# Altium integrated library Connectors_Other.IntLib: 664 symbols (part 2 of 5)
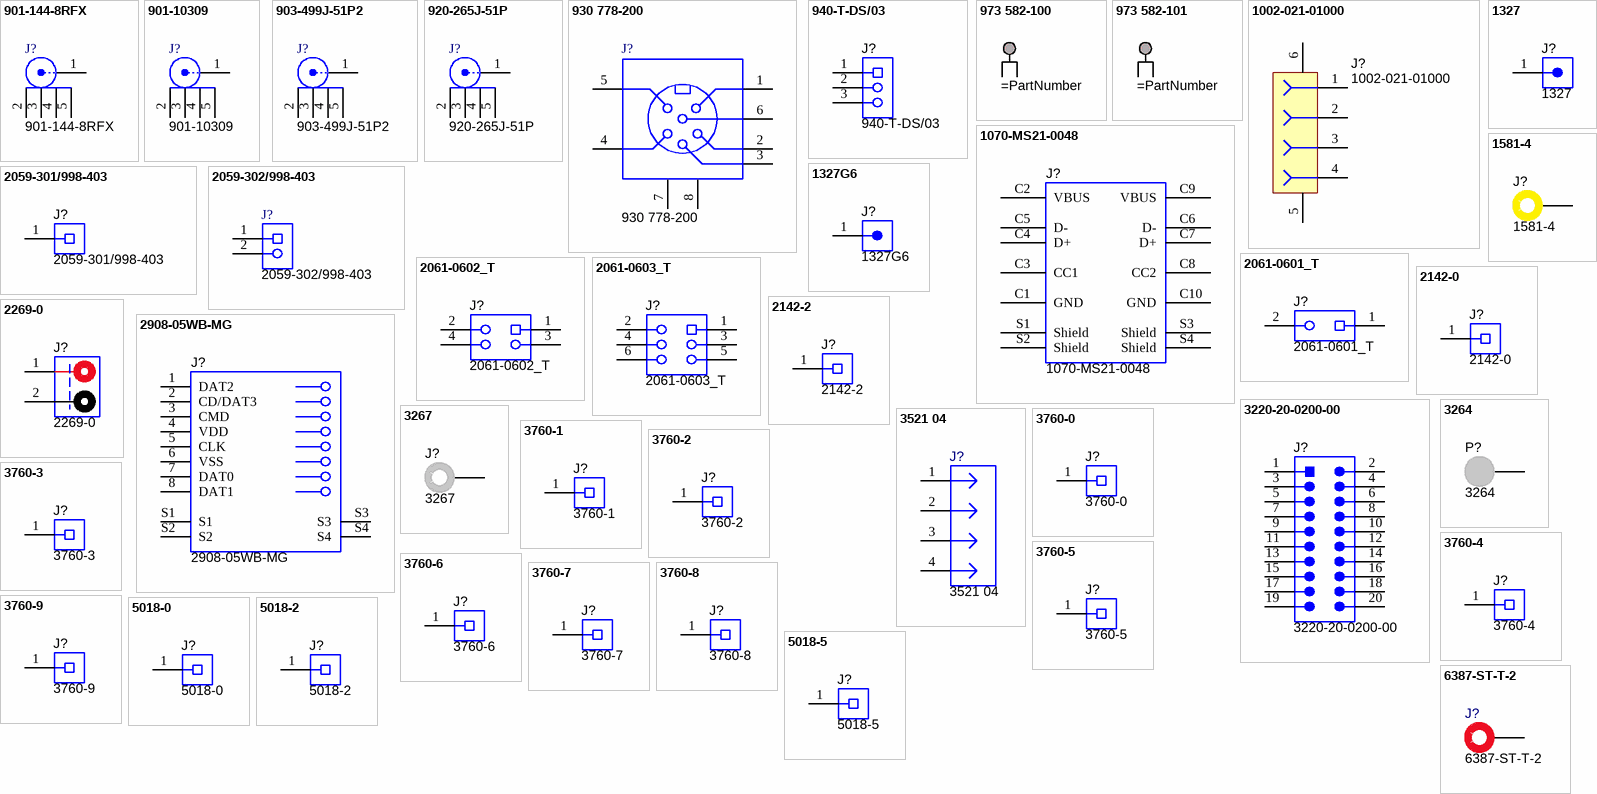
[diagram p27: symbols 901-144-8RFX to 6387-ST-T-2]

## 5018-0
designator J?
Hex Head Binding Post, 1x1, Black, TH; Manufacturer: Pomona Electronics; SymbolCreator: a0799628; CompType: Connector; Current_A: 30; Green_Lifecycle: Not Set; Green_REACh: Incomplete
footprint Pomona_5018-0
pins: 1

## 5018-2
designator J?
Hex Head Binding Post, 1x1, Red, TH; Manufacturer: Pomona Electronics; SymbolCreator: a0799628; CompType: Connector; Current_A: 30; Green_Lifecycle: Not Set; Green_REACh: Incomplete
footprint Pomona_5018-2
pins: 1

## 5018-5
designator J?
Hex Head Binding Post, 1x1, Green, TH; Manufacturer: Pomona Electronics; SymbolCreator: a0799628; CompType: Connector; Current_A: 30
footprint Pomona_5018-5
pins: 1

## 6387-ST-T-2
designator J?
Banana Jack For Sheathed Banana Plugs, 4mm, TH; Manufacturer: Pomona Electronics; SymbolCreator: a0412235; ContactFinish: Tin
footprint Pomona_6387-ST-T-2
pins: 1

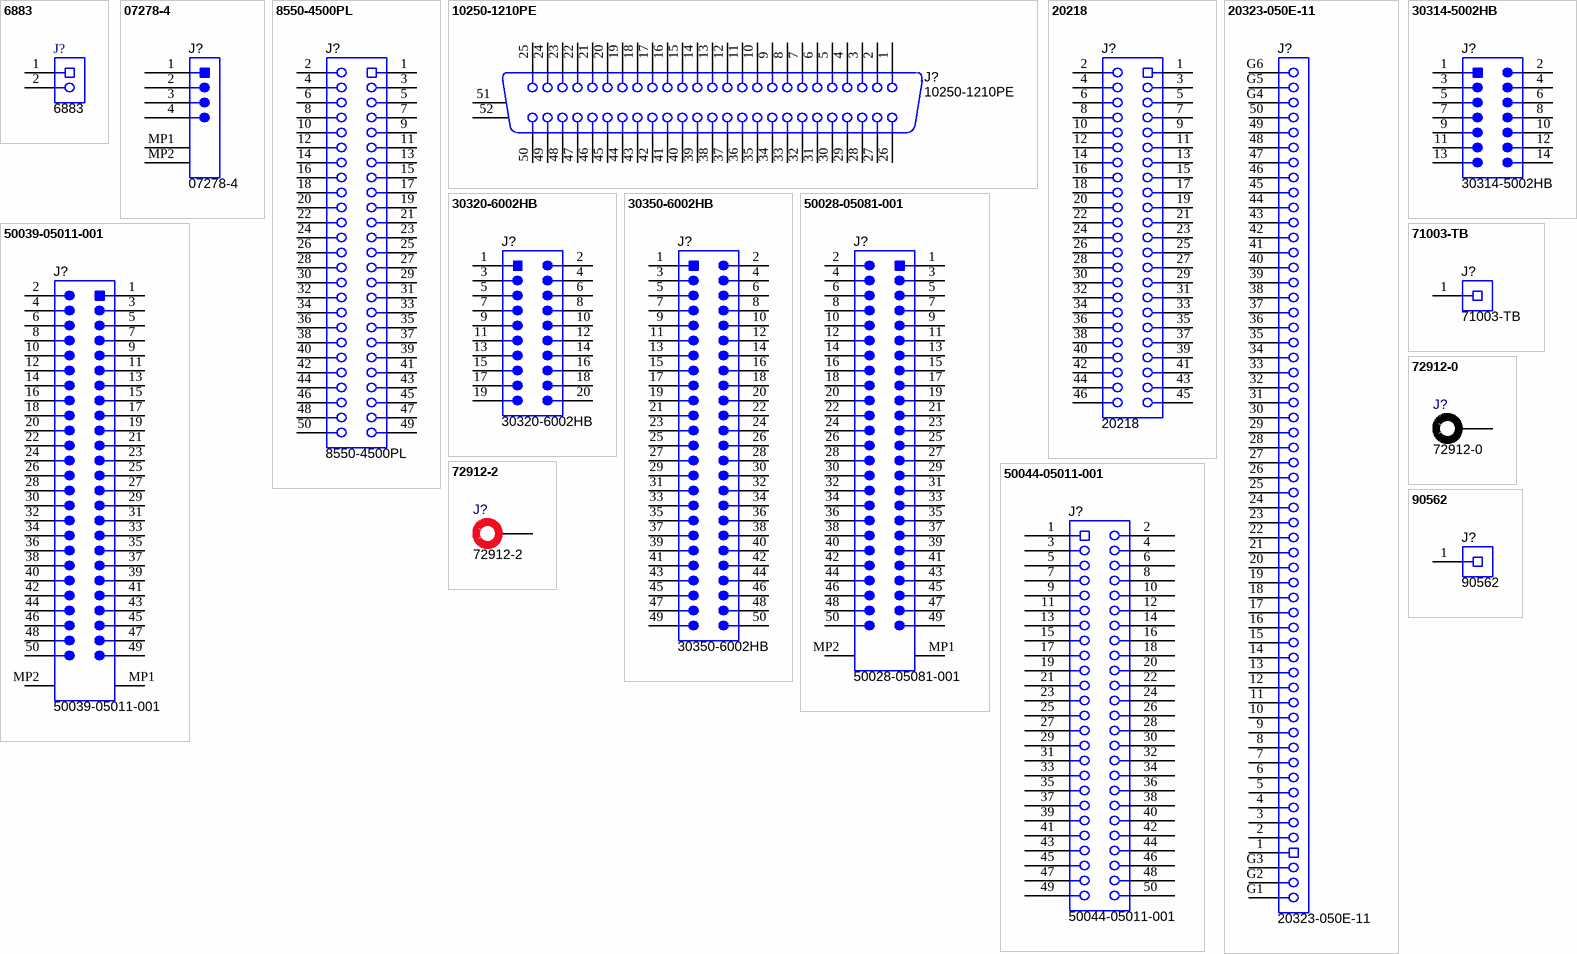
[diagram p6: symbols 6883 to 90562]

## 6883
designator J?
Dual Binding Posts with Base, 2x1, TH; Manufacturer: Pomona Electronics; SymbolCreator: a0412235; CompType: Connector; Green_Lifecycle: Not Set; Green_REACh: Incomplete
footprint Pomona_6883
pins: 1, 2

## 07278-4
designator J?
Header, 1mm, 4x1, R/A, SMT; Manufacturer: 4UCON Technology; SymbolCreator: Altium; Pitch_mm: 1; Gender: Male; ContactFinish: Tin; Voltage_V: 50; Cert_UL: Y
footprint 4UCON_07278-4
pins: 1, 2, 3, 4, MP1, MP2

## 8550-4500PL
designator J?
Receptacle, 2.54mm, 25x2, Gold, TH; Manufacturer: 3M; SymbolCreator: a0412235; Pitch_mm: 2.54; Gender: Female; Row_Count: 2
footprint 3M_8550-4500PL
pins: 1, 2, 3, 4, 5, 6, 7, 8, 9, 10, 11, 12, 13, 14, 15, 16, 17, 18, 19, 20, 21, 22, 23, 24, 25, 26, 27, 28, 29, 30, 31, 32, 33, 34, 35, 36, 37, 38, 39, 40, 41, 42, 43, 44, 45, 46, 47, 48, 49, 50

## 10250-1210PE
designator J?
Connector, Receptacle, D-Sub, 50POS, R/A, SMT; Manufacturer: 3M; SymbolCreator: a0412235
footprint CONN_3M_10250-1210PE
pins: 1, 2, 3, 4, 5, 6, 7, 8, 9, 10, 11, 12, 13, 14, 15, 16, 17, 18, 19, 20, 21, 22, 23, 24, 25, 26, 27, 28, 29, 30, 31, 32, 33, 34, 35, 36, 37, 38, 39, 40, 41, 42, 43, 44, 45, 46, 47, 48, 49, 50, 51, 52

## 20218
designator J?
Receptacle, 2.54 mm, 23x2, Gold, TH; Manufacturer: 4UCON Technology; SymbolCreator: Altium
footprint 4UCON_20218
pins: 1, 2, 3, 4, 5, 6, 7, 8, 9, 10, 11, 12, 13, 14, 15, 16, 17, 18, 19, 20, 21, 22, 23, 24, 25, 26, 27, 28, 29, 30, 31, 32, 33, 34, 35, 36, 37, 38, 39, 40, 41, 42, 43, 44, 45, 46

## 20323-050E-11
designator J?
FPL, Receptacle SMT 0.5 mm pitch, 50 pos; Manufacturer: I-PEX; SymbolCreator: a0799628
footprint I-PEX_20323-050E-11
pins: 1, 2, 3, 4, 5, 6, 7, 8, 9, 10, 11, 12, 13, 14, 15, 16, 17, 18, 19, 20, 21, 22, 23, 24, 25, 26, 27, 28, 29, 30, 31, 32, 33, 34, 35, 36, 37, 38, 39, 40, 41, 42, 43, 44, 45, 46, 47, 48, 49, 50, G1, G2, G3, G4, G5, G6

## 30314-5002HB
designator J?
Header(shrouded), 2.54mm, 7x2, Gold, R/A,  TH; Manufacturer: 3M; SymbolCreator: a0412235; Pitch_mm: 2.54; Gender: Male; Shrouded: Y; Row_Count: 2; Current_A: 1
footprint 3M_30314-5002
pins: 1, 2, 3, 4, 5, 6, 7, 8, 9, 10, 11, 12, 13, 14

## 30320-6002HB
designator J?
Straight Low Profile Header, 10x2 Position, 2.54 mm Pitch, TH; Manufacturer: 3M; SymbolCreator: a0412235
footprint 3M_30320-6002HB
pins: 1, 2, 3, 4, 5, 6, 7, 8, 9, 10, 11, 12, 13, 14, 15, 16, 17, 18, 19, 20

## 30350-6002HB
designator J?
Header (Shrouded), 2.54 mm, 25x2, Gold, TH; Manufacturer: 3M; SymbolCreator: a0799628
footprint 3M_30350-6002HB
pins: 1, 2, 3, 4, 5, 6, 7, 8, 9, 10, 11, 12, 13, 14, 15, 16, 17, 18, 19, 20, 21, 22, 23, 24, 25, 26, 27, 28, 29, 30, 31, 32, 33, 34, 35, 36, 37, 38, 39, 40, 41, 42, 43, 44, 45, 46, 47, 48, 49, 50

## 50028-05081-001
designator J?
Plug, 0.5mm, 25x2, Gold, SMT; Manufacturer: ACES Electronics; SymbolCreator: Altium; Pitch_mm: 0.5; Gender: Male; Row_Count: 2; Cert_UL: Y
footprint Aces_50028-050
pins: 1, 2, 3, 4, 5, 6, 7, 8, 9, 10, 11, 12, 13, 14, 15, 16, 17, 18, 19, 20, 21, 22, 23, 24, 25, 26, 27, 28, 29, 30, 31, 32, 33, 34, 35, 36, 37, 38, 39, 40, 41, 42, 43, 44, 45, 46, 47, 48, 49, 50, MP1, MP2

## 50039-05011-001
designator J?
Plug, 0.5mm, 25x2, Gold, SMD; Manufacturer: ACES Electronics; SymbolCreator: Altium; Pitch_mm: 0.5; Gender: Male; Shrouded: Y; Row_Count: 2; RowSpacing_mm: 3.675; Voltage_V: 50
footprint Aces_50039-05011-001
pins: 1, 2, 3, 4, 5, 6, 7, 8, 9, 10, 11, 12, 13, 14, 15, 16, 17, 18, 19, 20, 21, 22, 23, 24, 25, 26, 27, 28, 29, 30, 31, 32, 33, 34, 35, 36, 37, 38, 39, 40, 41, 42, 43, 44, 45, 46, 47, 48, 49, 50, MP1, MP2

## 50044-05011-001
designator J?
Receptacle, 0.5mm, 25x2, Gold, SMD; Manufacturer: ACES Electronics; SymbolCreator: Altium; Pitch_mm: 0.5; Gender: Female; Row_Count: 2; RowSpacing_mm: 4.2; Voltage_V: 50; Cert_UL: Y
footprint Aces_50044-05011-001
pins: 1, 2, 3, 4, 5, 6, 7, 8, 9, 10, 11, 12, 13, 14, 15, 16, 17, 18, 19, 20, 21, 22, 23, 24, 25, 26, 27, 28, 29, 30, 31, 32, 33, 34, 35, 36, 37, 38, 39, 40, 41, 42, 43, 44, 45, 46, 47, 48, 49, 50

## 71003-TB
designator J?
Locktite Copper Cone Screw Lug for Conductor Range 14-8, TH; Manufacturer: Thomas & Betts; SymbolCreator: a0799628; CompType: Connector; Gender: Female; Row_Count: 1; Cert_CSA: Y
footprint TB_71003
pins: 1

## 72912-0
designator J?
Banana Jack for Sheathed Plugs, Black, TH; Manufacturer: Pomona Electronics; SymbolCreator: a0412235
footprint Pomona_72912-0
pins: 1

## 72912-2
designator J?
Banana Jack for Sheathed Plugs, Red, TH; Manufacturer: Pomona Electronics; SymbolCreator: a0412235
footprint Pomona_72912-2
pins: 1

## 90562
designator J?
Connector Lug, wire range #6 ‐ 4/0, 600V; Manufacturer: Morris Products; SymbolCreator: a0799628; CompType: Receptacle
footprint Morris_90562
pins: 1

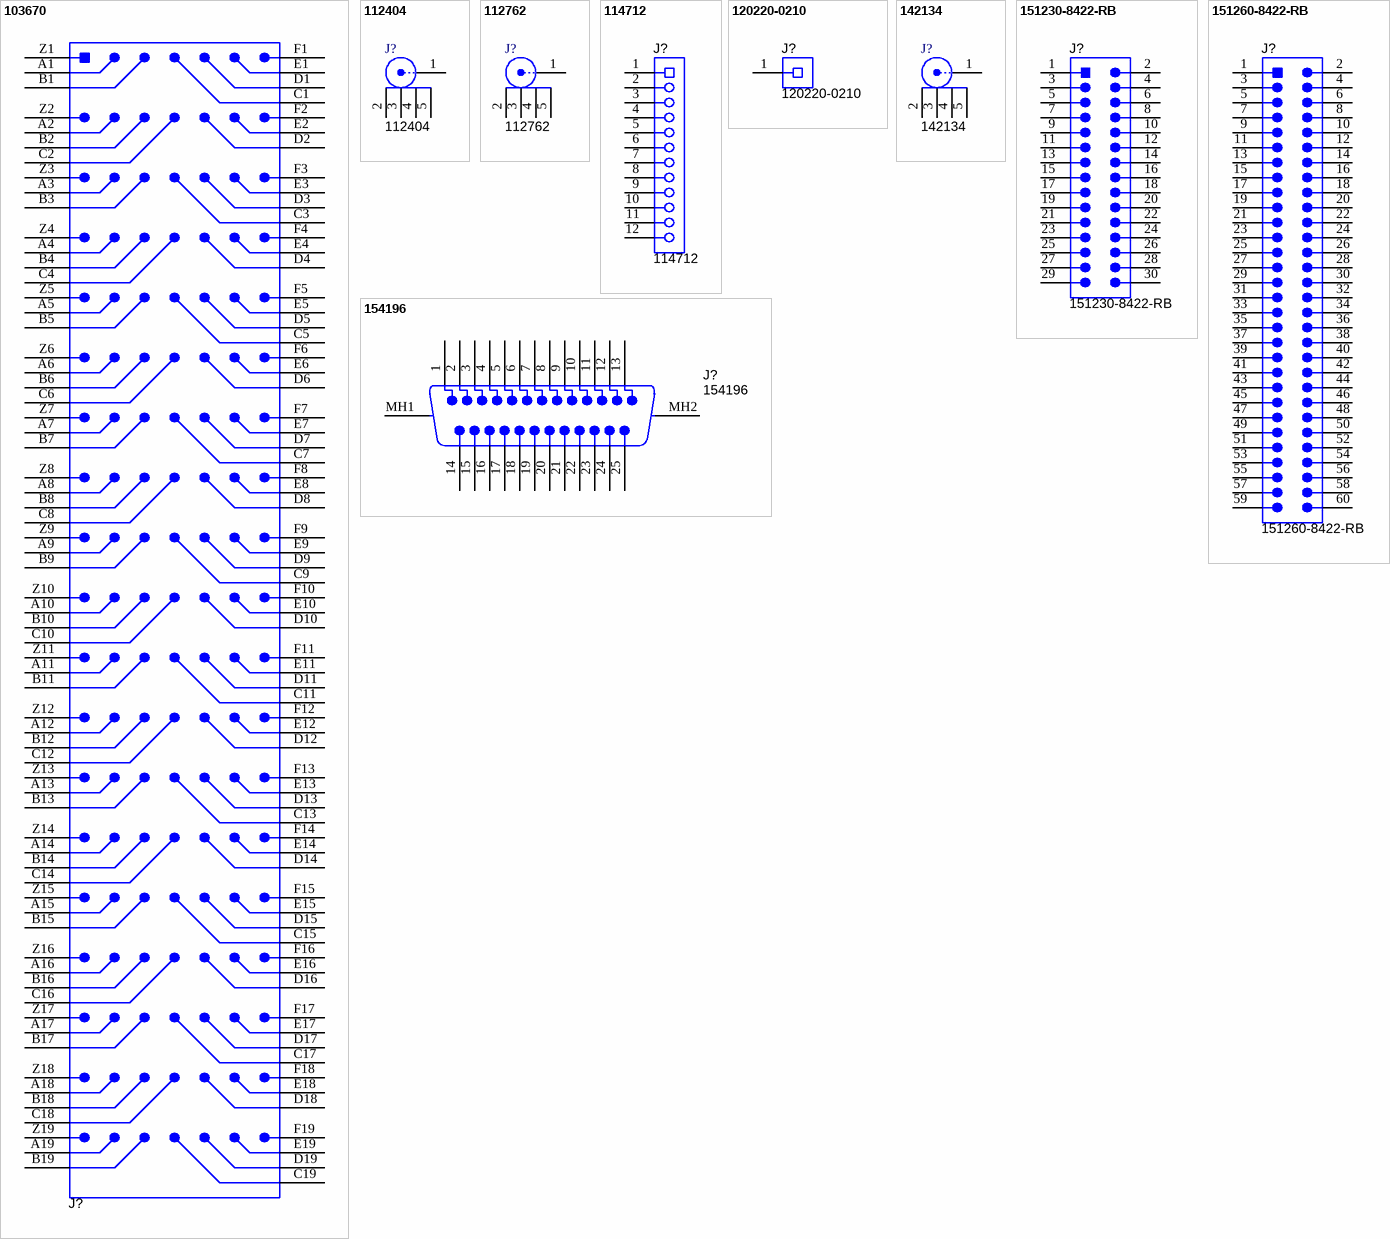
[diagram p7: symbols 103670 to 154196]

## 103670
designator J?  (value not drawn)
Header(shrouded), 2mm, 19x7, Gold, TH; Manufacturer: ERNI; SymbolCreator: Altium; Pitch_mm: 2; Gender: Male; Shrouded: Y; Row_Count: 7
footprint ERNI_103670
pins: A1, A2, A3, A4, A5, A6, A7, A8, A9, A10, A11, A12, A13, A14, A15, A16, A17, A18, A19, B1, B2, B3, B4, B5, B6, B7, B8, B9, B10, B11, B12, B13, B14, B15, B16, B17, B18, B19, C1, C2, C3, C4, C5, C6, C7, C8, C9, C10, C11, C12, C13, C14, C15, C16, C17, C18, C19, D1, D2, D3, D4, D5, D6, D7, D8, D9, D10, D11, D12, D13, D14, D15, D16, D17, D18, D19, E1, E2, E3, E4, E5, E6, E7, E8, E9, E10, E11, E12, E13, E14, E15, E16, E17, E18, E19, F1, F2, F3, F4, F5, F6, F7, F8, F9, F10, F11, F12, F13, F14, F15, F16, F17, F18, F19, Z1, Z2, Z3, Z4, Z5, Z6, Z7, Z8, Z9, Z10, Z11, Z12, Z13, Z14, Z15, Z16, Z17, Z18, Z19

## 112404
designator J?
Connector, TH, BNC; Manufacturer: Amphenol Connex; Green_Lifecycle: Not Set; Green_REACh: Incomplete
footprint Amphenol_112404
pins: 1, 2, 3, 4, 5

## 112762
designator J?
Connector, BNC 75 ohm, R/A, TH; Manufacturer: Amphenol Connex; SymbolCreator: X0208326; Gender: Female; ContactFinish: Gold
footprint Amphenol_112762
pins: 1, 2, 3, 4, 5

## 114712
designator J?
MicroStac Steckverb, 12 Pos, SMD; Manufacturer: ERNI; SymbolCreator: a0412235
footprint Microstack_12p_114712
pins: 1, 2, 3, 4, 5, 6, 7, 8, 9, 10, 11, 12

## 120220-0210
designator J?
Micro Universal Contact 1.3MM, SMD; Manufacturer: ITT Cannon; SymbolCreator: a0799628; CompType: Connector; Gender: Female; Row_Count: 1; ContactFinish: Gold
footprint Cannon_120220-0210
pins: 1

## 142134
designator J?
SMB Straight Plug, 50 Ohm, Gold, TH; Manufacturer: Amphenol RF; SymbolCreator: X0208326; Gender: Female; Voltage_V: 335
footprint Amphenol_142134
pins: 1, 2, 3, 4, 5

## 151230-8422-RB
designator J?
Header, 2mm, 15x2, Gold, TH; Manufacturer: 3M; SymbolCreator: a0412235
footprint 3M_151230-8422-RB
pins: 1, 2, 3, 4, 5, 6, 7, 8, 9, 10, 11, 12, 13, 14, 15, 16, 17, 18, 19, 20, 21, 22, 23, 24, 25, 26, 27, 28, 29, 30

## 151260-8422-RB
designator J?
Header, 2mm, 30x2, Gold, TH; Manufacturer: 3M; SymbolCreator: a0411947; Green_Lifecycle: Active; Green_REACh: Passed
footprint 3M_151260-8422-RB
pins: 1, 2, 3, 4, 5, 6, 7, 8, 9, 10, 11, 12, 13, 14, 15, 16, 17, 18, 19, 20, 21, 22, 23, 24, 25, 26, 27, 28, 29, 30, 31, 32, 33, 34, 35, 36, 37, 38, 39, 40, 41, 42, 43, 44, 45, 46, 47, 48, 49, 50, 51, 52, 53, 54, 55, 56, 57, 58, 59, 60

## 154196
designator J?
Connector, D-Sub, Male, R/A, 25 pin, SMT; Manufacturer: ERNI; SymbolCreator: Altium
footprint ERNI_154196
pins: 1, 2, 3, 4, 5, 6, 7, 8, 9, 10, 11, 12, 13, 14, 15, 16, 17, 18, 19, 20, 21, 22, 23, 24, 25, MH1, MH2

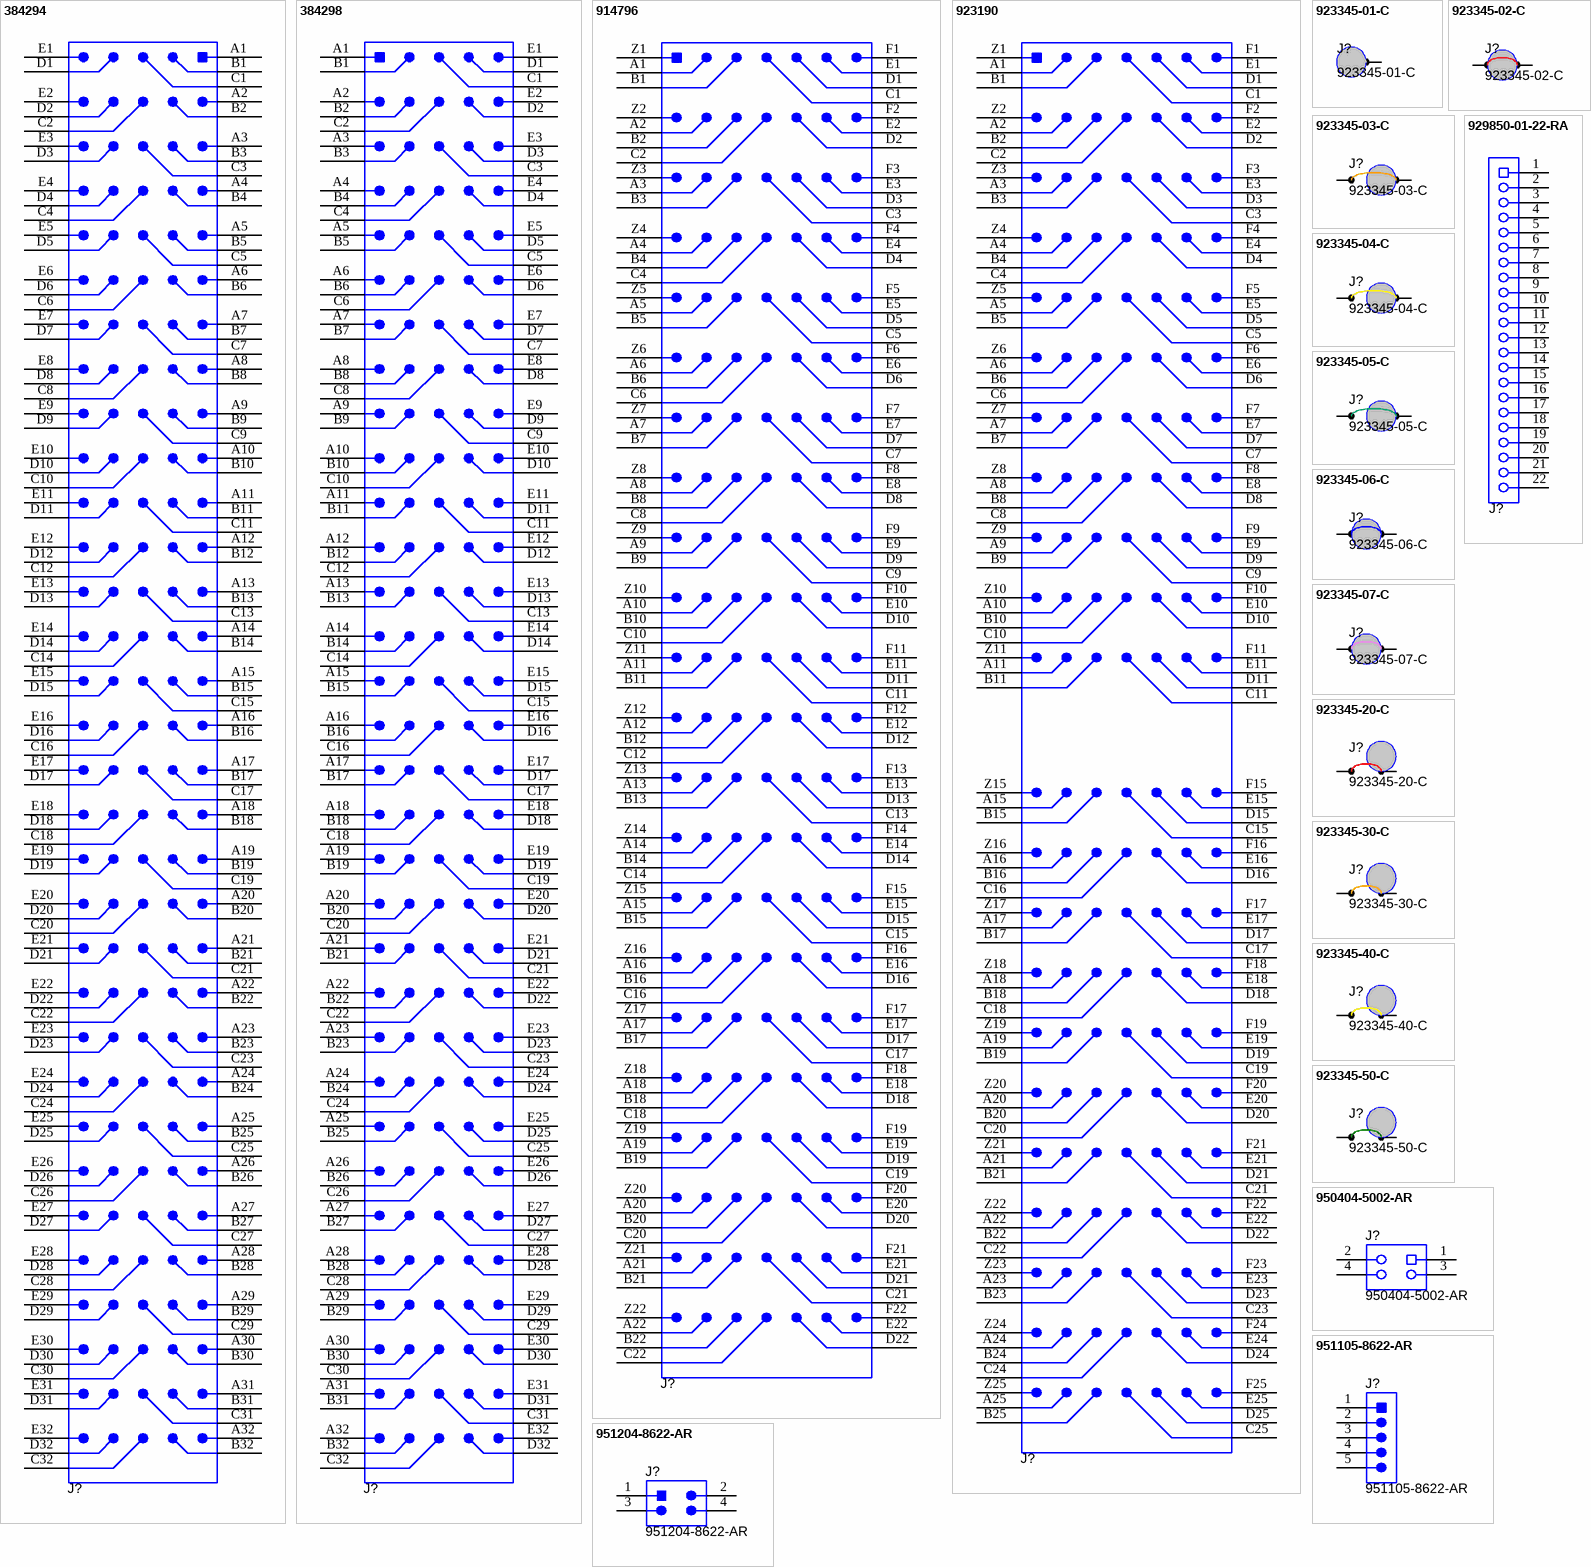
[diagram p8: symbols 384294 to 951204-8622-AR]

## 384294
designator J?  (value not drawn)
Header(shrouded), 2.54mm, 32x5, TH; Manufacturer: ERNI; SymbolCreator: Altium; Pitch_mm: 2.54; Gender: Male; Shrouded: Y; Row_Count: 5
footprint ERNI_384294
pins: A1, A2, A3, A4, A5, A6, A7, A8, A9, A10, A11, A12, A13, A14, A15, A16, A17, A18, A19, A20, A21, A22, A23, A24, A25, A26, A27, A28, A29, A30, A31, A32, B1, B2, B3, B4, B5, B6, B7, B8, B9, B10, B11, B12, B13, B14, B15, B16, B17, B18, B19, B20, B21, B22, B23, B24, B25, B26, B27, B28, B29, B30, B31, B32, C1, C2, C3, C4, C5, C6, C7, C8, C9, C10, C11, C12, C13, C14, C15, C16, C17, C18, C19, C20, C21, C22, C23, C24, C25, C26, C27, C28, C29, C30, C31, C32, D1, D2, D3, D4, D5, D6, D7, D8, D9, D10, D11, D12, D13, D14, D15, D16, D17, D18, D19, D20, D21, D22, D23, D24, D25, D26, D27, D28, D29, D30, D31, D32, E1, E2, E3, E4, E5, E6, E7, E8, E9, E10, E11, E12, E13, E14, E15, E16, E17, E18, E19, E20, E21, E22, E23, E24, E25, E26, E27, E28, E29, E30, E31, E32

## 384298
designator J?  (value not drawn)
Header, 2.54mm, 32x5, R/A, TH; Manufacturer: ERNI; SymbolCreator: Altium; Pitch_mm: 2.54; Gender: Male; Shrouded: Y; Row_Count: 5
footprint ERNI_384298
pins: A1, A2, A3, A4, A5, A6, A7, A8, A9, A10, A11, A12, A13, A14, A15, A16, A17, A18, A19, A20, A21, A22, A23, A24, A25, A26, A27, A28, A29, A30, A31, A32, B1, B2, B3, B4, B5, B6, B7, B8, B9, B10, B11, B12, B13, B14, B15, B16, B17, B18, B19, B20, B21, B22, B23, B24, B25, B26, B27, B28, B29, B30, B31, B32, C1, C2, C3, C4, C5, C6, C7, C8, C9, C10, C11, C12, C13, C14, C15, C16, C17, C18, C19, C20, C21, C22, C23, C24, C25, C26, C27, C28, C29, C30, C31, C32, D1, D2, D3, D4, D5, D6, D7, D8, D9, D10, D11, D12, D13, D14, D15, D16, D17, D18, D19, D20, D21, D22, D23, D24, D25, D26, D27, D28, D29, D30, D31, D32, E1, E2, E3, E4, E5, E6, E7, E8, E9, E10, E11, E12, E13, E14, E15, E16, E17, E18, E19, E20, E21, E22, E23, E24, E25, E26, E27, E28, E29, E30, E31, E32

## 914796
designator J?  (value not drawn)
Header(shrouded), 2mm, 22x7, Gold, TH; Manufacturer: ERNI; SymbolCreator: Altium; Pitch_mm: 2; Gender: Male; Shrouded: Y; Row_Count: 7
footprint ERNI_914796
pins: A1, A2, A3, A4, A5, A6, A7, A8, A9, A10, A11, A12, A13, A14, A15, A16, A17, A18, A19, A20, A21, A22, B1, B2, B3, B4, B5, B6, B7, B8, B9, B10, B11, B12, B13, B14, B15, B16, B17, B18, B19, B20, B21, B22, C1, C2, C3, C4, C5, C6, C7, C8, C9, C10, C11, C12, C13, C14, C15, C16, C17, C18, C19, C20, C21, C22, D1, D2, D3, D4, D5, D6, D7, D8, D9, D10, D11, D12, D13, D14, D15, D16, D17, D18, D19, D20, D21, D22, E1, E2, E3, E4, E5, E6, E7, E8, E9, E10, E11, E12, E13, E14, E15, E16, E17, E18, E19, E20, E21, E22, F1, F2, F3, F4, F5, F6, F7, F8, F9, F10, F11, F12, F13, F14, F15, F16, F17, F18, F19, F20, F21, F22, Z1, Z2, Z3, Z4, Z5, Z6, Z7, Z8, Z9, Z10, Z11, Z12, Z13, Z14, Z15, Z16, Z17, Z18, Z19, Z20, Z21, Z22

## 923190
designator J?  (value not drawn)
Header(shrouded), 2mm, 154 Pos, Gold, TH; Manufacturer: ERNI; SymbolCreator: Altium; Pitch_mm: 2; Gender: Male; Shrouded: Y; Row_Count: 7
footprint ERNI_923190
pins: A1, A2, A3, A4, A5, A6, A7, A8, A9, A10, A11, A15, A16, A17, A18, A19, A20, A21, A22, A23, A24, A25, B1, B2, B3, B4, B5, B6, B7, B8, B9, B10, B11, B15, B16, B17, B18, B19, B20, B21, B22, B23, B24, B25, C1, C2, C3, C4, C5, C6, C7, C8, C9, C10, C11, C15, C16, C17, C18, C19, C20, C21, C22, C23, C24, C25, D1, D2, D3, D4, D5, D6, D7, D8, D9, D10, D11, D15, D16, D17, D18, D19, D20, D21, D22, D23, D24, D25, E1, E2, E3, E4, E5, E6, E7, E8, E9, E10, E11, E15, E16, E17, E18, E19, E20, E21, E22, E23, E24, E25, F1, F2, F3, F4, F5, F6, F7, F8, F9, F10, F11, F15, F16, F17, F18, F19, F20, F21, F22, F23, F24, F25, Z1, Z2, Z3, Z4, Z5, Z6, Z7, Z8, Z9, Z10, Z11, Z15, Z16, Z17, Z18, Z19, Z20, Z21, Z22, Z23, Z24, Z25

## 923345-01-C
designator J?
Jumper Wire, 100mil spacing, pkg of 200, TH; Manufacturer: 3M; SymbolCreator: Altium; Green_Lifecycle: Active; Green_REACh: Passed
footprint 3M_923345-01-C
pins: 1, 2

## 923345-02-C
designator J?
Jumper Wire, 200mil spacing, Red, pkg of 200; Manufacturer: 3M; SymbolCreator: a0412235; Green_Lifecycle: Active; Green_REACh: Passed
footprint 923345-02-C
pins: 1, 2

## 923345-03-C
designator J?
Jumper Wire, 300mil spacing, Orange, pkg of 200; Manufacturer: 3M; SymbolCreator: a0412235; Green_Lifecycle: Active; Green_REACh: Passed
footprint 923345-03-C
pins: 1, 2

## 923345-04-C
designator J?
Jumper Wire, 400 mil Spacing, Yellow, Pkg of 200; Manufacturer: 3M; SymbolCreator: Altium; Green_Lifecycle: Active; Green_REACh: Passed
footprint 3M_923345-04-C
pins: 1, 2

## 923345-05-C
designator J?
Jumper Wire, 500mil spacing, Green, pkg of 200; Manufacturer: 3M; SymbolCreator: a0412235; Green_Lifecycle: Active; Green_REACh: Passed
footprint 923345-05-C
pins: 1, 2

## 923345-06-C
designator J?
Jumper Wire, 600mil spacing, Blue, pkg of 150, TH; Manufacturer: 3M; SymbolCreator: a0412235; Green_Lifecycle: Active; Green_REACh: Passed
footprint CONN_923345-06-C
pins: 1, 2

## 923345-07-C
designator J?
Jumper Wire, 700mil spacing, Violet, pkg of 150, TH; Manufacturer: 3M; SymbolCreator: a0412235; Green_Lifecycle: Active; Green_REACh: Passed
footprint CONN_923345-07-C
pins: 1, 2

## 923345-20-C
designator J?
Jumper Wire, 2" spacing, Red, pkg of 100, TH; Manufacturer: 3M; SymbolCreator: a0411947; Pitch_mm: 50.8; Gender: Male; Row_Count: 1; ContactFinish: Tin; Green_Lifecycle: Active; Green_REACh: Passed
footprint 3M_923345-20-C
pins: 1, 2

## 923345-30-C
designator J?
Jumper Wire, 3" spacing, Orange, pkg of 75, TH; Manufacturer: 3M; SymbolCreator: a0411947; Pitch_mm: 76.2; Gender: Male; Row_Count: 1; ContactFinish: Tin
footprint 3M_923345-30-C
pins: 1, 2

## 923345-40-C
designator J?
Jumper Wire, 4" spacing, Yellow, pkg of 75, TH; Manufacturer: 3M; SymbolCreator: a0411947; Pitch_mm: 101.6; Gender: Male; Row_Count: 1; ContactFinish: Tin
footprint 3M_923345-40-C
pins: 1, 2

## 923345-50-C
designator J?
Jumper Wire, 5" spacing, Green, pkg of 75, TH; Manufacturer: 3M; SymbolCreator: a0411947; Pitch_mm: 127; Gender: Male; Row_Count: 1; ContactFinish: Tin
footprint 3M_923345-50-C
pins: 1, 2

## 929850-01-22-RA
designator J?  (value not drawn)
Receptacle, 2.54mm, 22x1, Gold, TH; Manufacturer: 3M; SymbolCreator: Altium; Pitch_mm: 2.54; Gender: Female; Row_Count: 1; Current_A: 2; Cert_UL: Y
footprint 3M_929850-01-22
pins: 1, 2, 3, 4, 5, 6, 7, 8, 9, 10, 11, 12, 13, 14, 15, 16, 17, 18, 19, 20, 21, 22

## 950404-5002-AR
designator J?
Receptacle, 2mm, 2x2, Gold, R/A, TH; Manufacturer: 3M; SymbolCreator: a0411947; Pitch_mm: 2; Gender: Female
footprint 3M_950404-5002-AR
pins: 1, 2, 3, 4

## 951105-8622-AR
designator J?
Header, 2mm, 5x1, Gold, Black, TH; Manufacturer: 3M; SymbolCreator: a0412235; Pitch_mm: 2; Gender: Male; Row_Count: 1; Voltage_V: 1000; Cert_UL: Y
footprint 3M_951105-8622-AR
pins: 1, 2, 3, 4, 5

## 951204-8622-AR
designator J?
Header, 2mm, 2x2, Gold, TH; Manufacturer: 3M; SymbolCreator: a0412235; Pitch_mm: 2; Gender: Male; Shrouded: N; Current_A: 1; Voltage_V: 1000; Cert_UL: Y
footprint 3M_951204-8622
pins: 1, 2, 3, 4

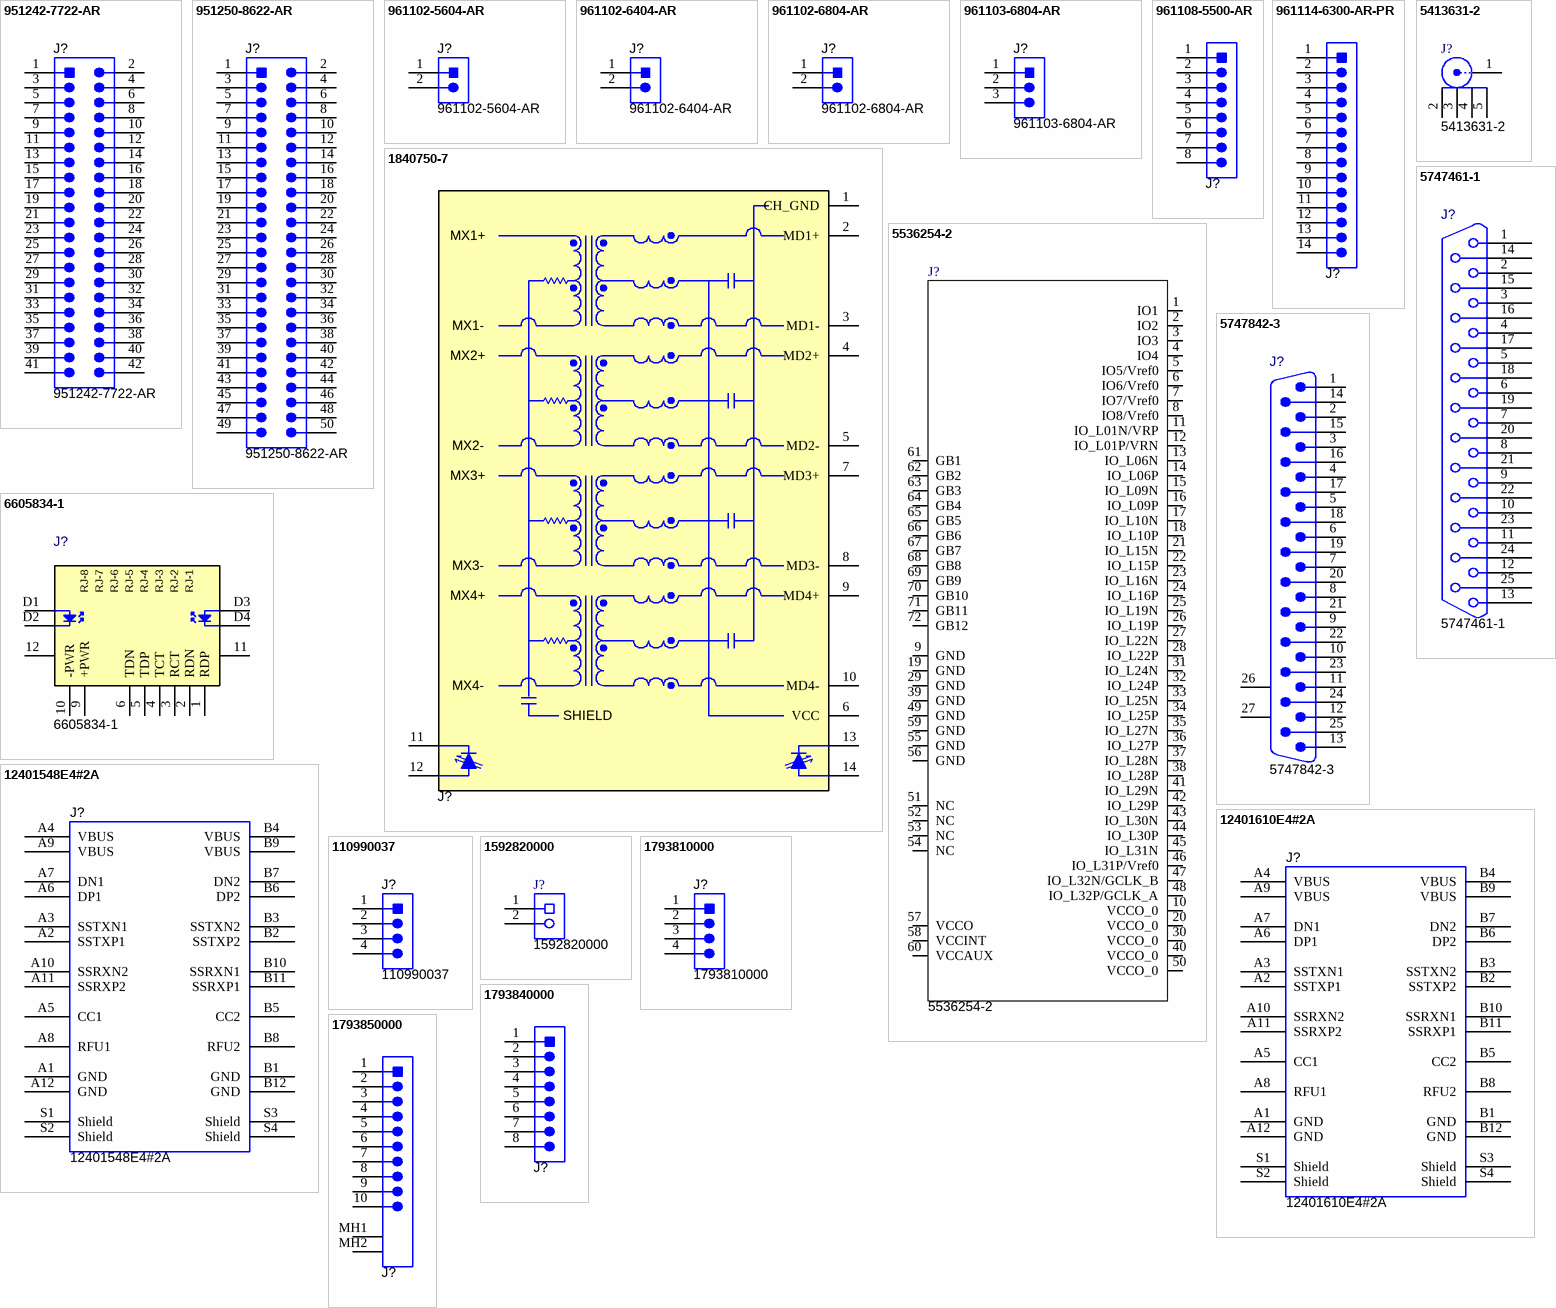
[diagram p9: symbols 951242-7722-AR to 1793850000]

## 951242-7722-AR
designator J?
Header, 2mm, 21x2 selectively Gold plated, R/A, TH; Manufacturer: 3M; SymbolCreator: a0412235
footprint CONN_3M_951242-7722-AR
pins: 1, 2, 3, 4, 5, 6, 7, 8, 9, 10, 11, 12, 13, 14, 15, 16, 17, 18, 19, 20, 21, 22, 23, 24, 25, 26, 27, 28, 29, 30, 31, 32, 33, 34, 35, 36, 37, 38, 39, 40, 41, 42

## 951250-8622-AR
designator J?
Header, 2mm, 25x2, Gold, TH; Manufacturer: 3M; SymbolCreator: a0799628; Pitch_mm: 2; Gender: Male; Shrouded: N; Current_A: 1; Voltage_V: 1000; Cert_UL: Y
footprint 3M_951250-8622
pins: 1, 2, 3, 4, 5, 6, 7, 8, 9, 10, 11, 12, 13, 14, 15, 16, 17, 18, 19, 20, 21, 22, 23, 24, 25, 26, 27, 28, 29, 30, 31, 32, 33, 34, 35, 36, 37, 38, 39, 40, 41, 42, 43, 44, 45, 46, 47, 48, 49, 50

## 961102-5604-AR
designator J?
Header, 2.54mm, 2x1, Gold, R/A, TH; Manufacturer: 3M; SymbolCreator: a0412235; Pitch_mm: 2.54; Gender: Male; Shrouded: N; Row_Count: 1; Current_A: 2; Cert_UL: Y
footprint 3M_961102-5604-xx
pins: 1, 2
1 alternate drawing of the same symbol

## 961102-6404-AR
designator J?
Header, 2.54mm, 2x1, TH; Manufacturer: 3M; SymbolCreator: a0412235; Pitch_mm: 2.54; Gender: Male; Shrouded: N; Row_Count: 1; ContactFinish: Gold; Current_A: 2; Voltage_V: 1000; Cert_UL: Y; Green_Lifecycle: Active; Green_REACh: Passed
footprint 3M_961102-6404-AR
pins: 1, 2
1 alternate drawing of the same symbol

## 961102-6804-AR
designator J?
Header, 2.54mm, 2x1, Gold, TH; Manufacturer: 3M; SymbolCreator: a0412235; Pitch_mm: 2.54; Gender: Male; Shrouded: N; Row_Count: 1; Current_A: 2; Cert_UL: Y
footprint 3M_961102-68
pins: 1, 2
1 alternate drawing of the same symbol

## 961103-6804-AR
designator J?
Header, 2.54mm, 3x1, Gold, TH; Manufacturer: 3M; SymbolCreator: a0799628; Pitch_mm: 2.54; Gender: Male; Shrouded: N; Row_Count: 1; Current_A: 2; Cert_UL: Y
footprint 3M_961103-68
pins: 1, 2, 3
3 alternate drawings of the same symbol

## 961108-5500-AR
designator J?  (value not drawn)
Header, 100mil, 8x1, Gold, R/A, SMT; Manufacturer: 3M; SymbolCreator: a0411947
footprint 961108-5500-AR
pins: 1, 2, 3, 4, 5, 6, 7, 8

## 961114-6300-AR-PR
designator J?  (value not drawn)
Header, 2.54mm, 14x1, Gold, SMD; Manufacturer: 3M; SymbolCreator: a0411947; Pitch_mm: 2.54; Gender: Male; Shrouded: N; Row_Count: 1; Current_A: 2; Voltage_V: 1000; Cert_UL: Y
footprint 3M_961114-6300
pins: 1, 2, 3, 4, 5, 6, 7, 8, 9, 10, 11, 12, 13, 14

## 1840750-7
designator J?  (value not drawn)
MagJack Single Non-PoE, 14Pos, TH; Manufacturer: TRP Connector; SymbolCreator: Altium; CompType: Connector; Gender: Female; Row_Count: 1; ContactFinish: Gold; Cert_UL: Y
footprint TRP_1840750-7
pins: 1 CH_GND, 2 MD1+, 3 MD1-, 4 MD2+, 5 MD2-, 6 VCC, 7 MD3+, 8 MD3-, 9 MD4+, 10 MD4-, 11, 12, 13, 14

## 5413631-2
designator J?
Connector, TH, BNC Right angle, 50 ohm gold; Manufacturer: AMP
footprint 5413631-2
pins: 1, 2, 3, 4, 5

## 5536254-2
designator J?
Connector for ADC14155, SMT; Manufacturer: AMP; Note: Mouser_PN = 571-5536254-2; U/M: EA
footprint AMP5536254-2
pins: 1 IO1, 2 IO2, 3 IO3, 4 IO4, 5 IO5/Vref0, 6 IO6/Vref0, 7 IO7/Vref0, 8 IO8/Vref0, 9 GND, 10 VCCO_0, 11 IO_L01N/VRP, 12 IO_L01P/VRN, 13 IO_L06N, 14 IO_L06P, 15 IO_L09N, 16 IO_L09P, 17 IO_L10N, 18 IO_L10P, 19 GND, 20 VCCO_0, 21 IO_L15N, 22 IO_L15P, 23 IO_L16N, 24 IO_L16P, 25 IO_L19N, 26 IO_L19P, 27 IO_L22N, 28 IO_L22P, 29 GND, 30 VCCO_0, 31 IO_L24N, 32 IO_L24P, 33 IO_L25N, 34 IO_L25P, 35 IO_L27N, 36 IO_L27P, 37 IO_L28N, 38 IO_L28P, 39 GND, 40 VCCO_0, 41 IO_L29N, 42 IO_L29P, 43 IO_L30N, 44 IO_L30P, 45 IO_L31N, 46 IO_L31P/Vref0, 47 IO_L32N/GCLK_B, 48 IO_L32P/GCLK_A, 49 GND, 50 VCCO_0, 51 NC, 52 NC, 53 NC, 54 NC, 55 GND, 56 GND, 57 VCCO, 58 VCCINT, 59 GND, 60 VCCAUX, 61 GB1, 62 GB2, 63 GB3, 64 GB4, 65 GB5, 66 GB6, 67 GB7, 68 GB8, 69 GB9, 70 GB10, 71 GB11, 72 GB12

## 5747461-1
designator J?
Connector, TH, DB25 parallel port, plastic, right angle; Manufacturer: AMP
footprint Amp_DB25
pins: 1, 2, 3, 4, 5, 6, 7, 8, 9, 10, 11, 12, 13, 14, 15, 16, 17, 18, 19, 20, 21, 22, 23, 24, 25

## 5747842-3
designator J?
Connector, TH, DB25 parallel port, plastic, right angle; Manufacturer: AMP; U/M: EA
footprint 5747842-3
pins: 1, 2, 3, 4, 5, 6, 7, 8, 9, 10, 11, 12, 13, 14, 15, 16, 17, 18, 19, 20, 21, 22, 23, 24, 25, 26 MH1, 27 MH2

## 6605834-1
designator J?
MAG45 Modular Jack, Shielded, with resistor LEDs; Manufacturer: TRP Connector; SymbolCreator: a0411947; CompType: Connector
footprint TRP_6605834
pins: 1 RDP, 2 RDN, 3 RCT, 4 TCT, 5 TDP, 6 TDN, 9 +PWR, 10 -PWR, 11, 12, D1, D2, D3, D4 D3

## 12401548E4#2A
designator J?
Connector, Receptacle, USB Type C, R/A, TH; Manufacturer: Amphenol Canada; SymbolCreator: Altium; Gender: Female; ContactFinish: Gold
footprint Amphenol_12401548E4#2A
pins: A1 GND, A2 SSTXP1, A3 SSTXN1, A4 VBUS, A5 CC1, A6 DP1, A7 DN1, A8 RFU1, A9 VBUS, A10 SSRXN2, A11 SSRXP2, A12 GND, B1 GND, B2 SSTXP2, B3 SSTXN2, B4 VBUS, B5 CC2, B6 DP2, B7 DN2, B8 RFU2, B9 VBUS, B10 SSRXN1, B11 SSRXP1, B12 GND, S1 Shield, S2 Shield, S3 Shield, S4 Shield

## 12401610E4#2A
designator J?
Receptacle, 0.5mm, USB TYPE C, R/A, SMT; Manufacturer: Amphenol Canada; SymbolCreator: Altium; Pitch_mm: 0.5; Gender: Female; Row_Count: 2; ContactFinish: Tin; Current_A: 5; Cert_UL: Y; Green_Lifecycle: Not Set; Green_REACh: Incomplete
footprint Amphenol_12401610E4_2A
pins: A1 GND, A2 SSTXP1, A3 SSTXN1, A4 VBUS, A5 CC1, A6 DP1, A7 DN1, A8 RFU1, A9 VBUS, A10 SSRXN2, A11 SSRXP2, A12 GND, B1 GND, B2 SSTXP2, B3 SSTXN2, B4 VBUS, B5 CC2, B6 DP2, B7 DN2, B8 RFU2, B9 VBUS, B10 SSRXN1, B11 SSRXP1, B12 GND, S1 Shield, S2 Shield, S3 Shield, S4 Shield

## 110990037
designator J?
Header(shrouded), 2mm, 4x1, Tin, R/A, TH; Manufacturer: SEEED; SymbolCreator: a0412235; Pitch_mm: 2; Gender: Male; Shrouded: Y; Row_Count: 1; Voltage_V: 250
footprint SEEED_110990037
pins: 1, 2, 3, 4

## 1592820000
designator J?
Terminal Block, 10.76x17x11 mm, 2POS, 26-12AWG, TH; Manufacturer: Weidmuller; SymbolCreator: a0412235; Green_Lifecycle: Not Set; Green_REACh: Incomplete
footprint WEIDMULLER_LP5-08-2-90
pins: 1, 2

## 1793810000
designator J?
TERM BLK HDR PCB 4POS 3.81MM GRN, TH; Manufacturer: Weidmuller; SymbolCreator: a0412235; CompType: Terminal Block
footprint Weidmuller_1793810000
pins: 1, 2, 3, 4

## 1793840000
designator J?  (value not drawn)
TERM BLK HDR PCB 8POS 3.81MM GRN, TH; Manufacturer: Weidmuller; SymbolCreator: a0411947; CompType: Terminal Block; Green_Lifecycle: Not Set; Green_REACh: Incomplete
footprint Weidmuller_1793840000
pins: 1, 2, 3, 4, 5, 6, 7, 8

## 1793850000
designator J?  (value not drawn)
Header(shrouded), 3.81mm, 10x1, Tin, TH; Manufacturer: Weidmuller; SymbolCreator: Altium; Pitch_mm: 3.81; Gender: Male; Shrouded: Y; Row_Count: 1; Current_A: 17.5; Voltage_V: 320
footprint Weidmuller_1793850000
pins: 1, 2, 3, 4, 5, 6, 7, 8, 9, 10, MH1, MH2

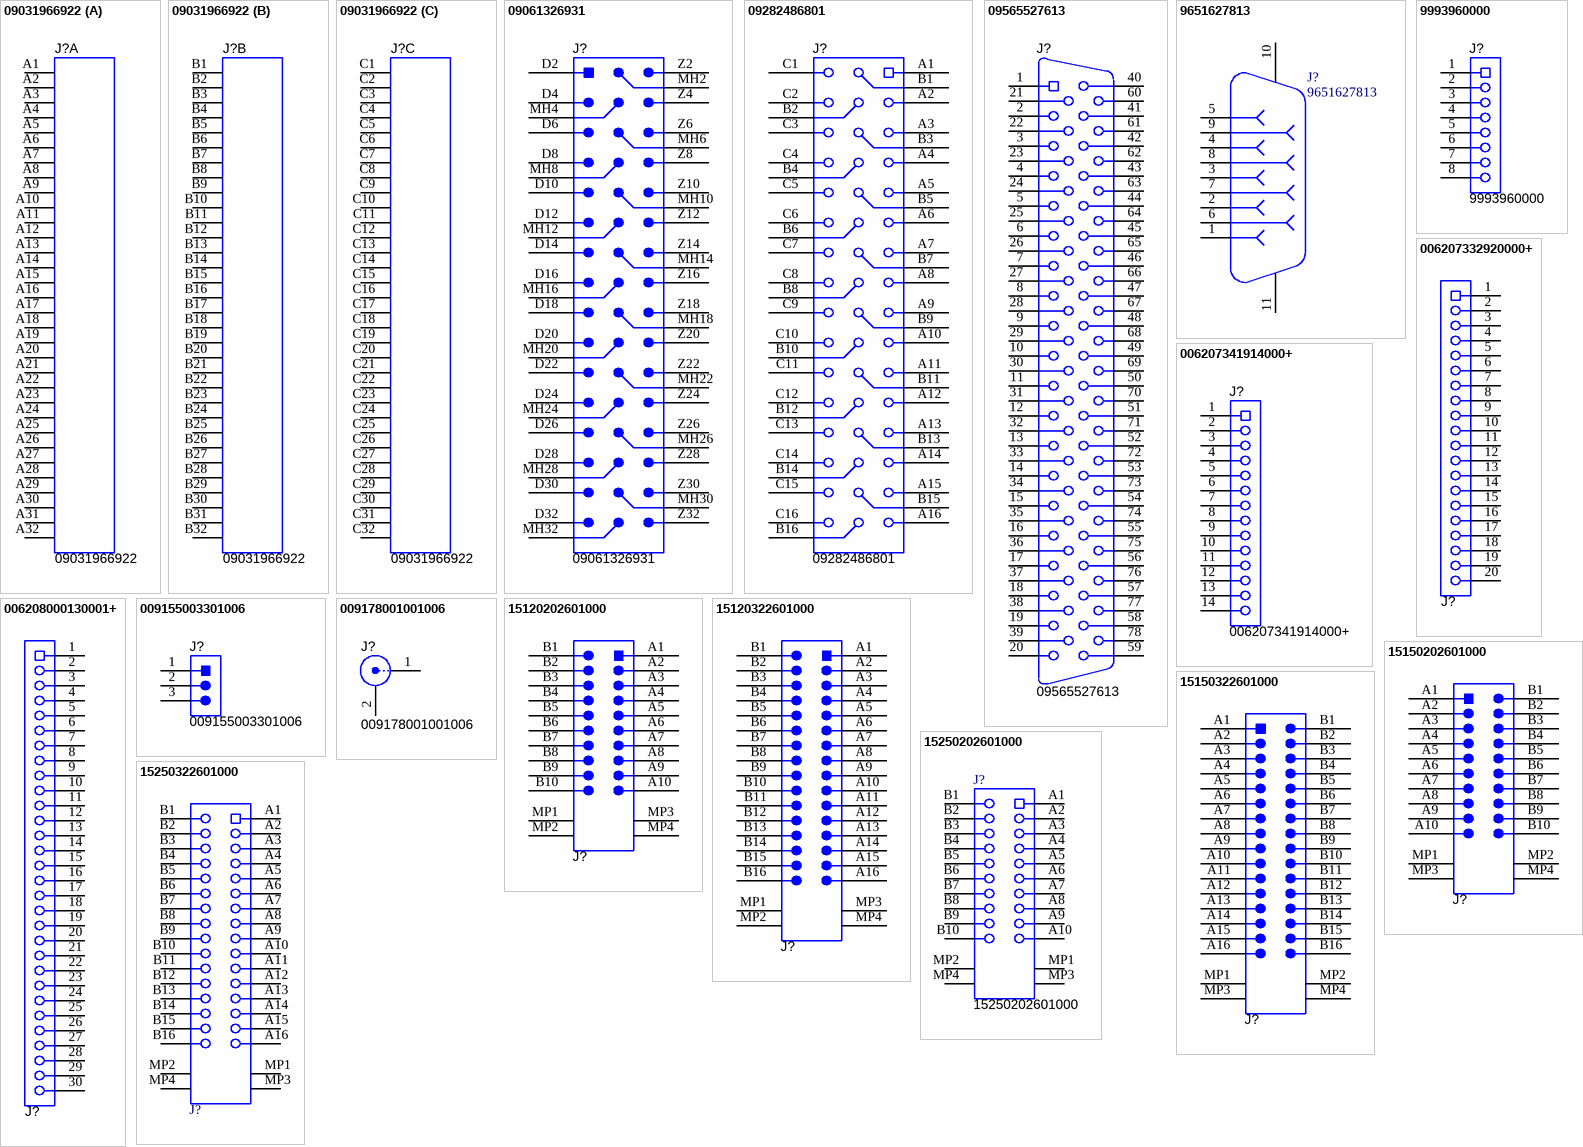
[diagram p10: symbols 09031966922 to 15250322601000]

## 09031966922
designator J?
DIN 41612, 100mil, Male, 32x3, TH; Manufacturer: Harting; SymbolCreator: a0799628; CompType: Connector
footprint CONN_09-03-196-6922
part A pins: A1 1, A2 2, A3 3, A4 4, A5 5, A6 6, A7 7, A8 8, A9 9, A10 10, A11 11, A12 12, A13 13, A14 14, A15 15, A16 16, A17 17, A18 18, A19 19, A20 20, A21 21, A22 22, A23 23, A24 24, A25 25, A26 26, A27 27, A28 28, A29 29, A30 30, A31 31, A32 32
part B pins: B1 1, B2 2, B3 3, B4 4, B5 5, B6 6, B7 7, B8 8, B9 9, B10 10, B11 11, B12 12, B13 13, B14 14, B15 15, B16 16, B17 17, B18 18, B19 19, B20 20, B21 21, B22 22, B23 23, B24 24, B25 25, B26 26, B27 27, B28 28, B29 29, B30 30, B31 31, B32 32
part C pins: C1 1, C2 2, C3 3, C4 4, C5 5, C6 6, C7 7, C8 8, C9 9, C10 10, C11 11, C12 12, C13 13, C14 14, C15 15, C16 16, C17 17, C18 18, C19 19, C20 20, C21 21, C22 22, C23 23, C24 24, C25 25, C26 26, C27 27, C28 28, C29 29, C30 30, C31 31, C32 32

## 09061326931
designator J?
Header(Shrouded), 5.08mm, 16x3, Gold, R/A, TH; Manufacturer: Harting; SymbolCreator: Altium; Pitch_mm: 5.08; Gender: Male; Shrouded: Y; Row_Count: 3
footprint Harting_09061326931
pins: D2, D4, D6, D8, D10, D12, D14, D16, D18, D20, D22, D24, D26, D28, D30, D32, MH2, MH4, MH6, MH8, MH10, MH12, MH14, MH16, MH18, MH20, MH22, MH24, MH26, MH28, MH30, MH32, Z2, Z4, Z6, Z8, Z10, Z12, Z14, Z16, Z18, Z20, Z22, Z24, Z26, Z28, Z30, Z32

## 09282486801
designator J?
Receptacle, 2.54mm, 16x3, R/A, Gold, TH; Manufacturer: Harting; SymbolCreator: Altium; Pitch_mm: 2.54; Gender: Female; Row_Count: 3; Current_A: 2; Cert_UL: Y
footprint Harting_09282486801
pins: A1, A2, A3, A4, A5, A6, A7, A8, A9, A10, A11, A12, A13, A14, A15, A16, B1, B2, B3, B4, B5, B6, B7, B8, B9, B10, B11, B12, B13, B14, B15, B16, C1, C2, C3, C4, C5, C6, C7, C8, C9, C10, C11, C12, C13, C14, C15, C16

## 09565527613
designator J?
D-SUB CONN, 78 Pins, Tin, R/A, TH; Manufacturer: Harting; SymbolCreator: a0411947; Pitch_mm: 2.41; Gender: Female; Row_Count: 4; RowSpacing_mm: 2.08; Current_A: 2
footprint Harting_09565527613
pins: 1, 2, 3, 4, 5, 6, 7, 8, 9, 10, 11, 12, 13, 14, 15, 16, 17, 18, 19, 20, 21, 22, 23, 24, 25, 26, 27, 28, 29, 30, 31, 32, 33, 34, 35, 36, 37, 38, 39, 40, 41, 42, 43, 44, 45, 46, 47, 48, 49, 50, 51, 52, 53, 54, 55, 56, 57, 58, 59, 60, 61, 62, 63, 64, 65, 66, 67, 68, 69, 70, 71, 72, 73, 74, 75, 76, 77, 78

## 9651627813
designator J?
D-Sub-9, 11Pos, Male, Screw Lock, TH; Manufacturer: Harting; SymbolCreator: x0208326; CompType: D-Sub; Pitch_mm: 2.74; Gender: Female; Row_Count: 2; RowSpacing_mm: 2.54; ContactFinish: Steel
footprint Harting_9651627813
pins: 1, 2, 3, 4, 5, 6, 7, 8, 9, 10, 11

## 9993960000
designator J?
Terminal Block, 5.08mm, 8x1, Black, TH; Manufacturer: Weidmuller; SymbolCreator: a0411947; Pitch_mm: 5.08; Gender: Female; Row_Count: 1; Current_A: 18; Voltage_V: 300; Cert_CSA: Y
footprint Weidmuller_9993960000
pins: 1, 2, 3, 4, 5, 6, 7, 8

## 006207332920000+
designator J?  (value not drawn)
Receptacle, 1.25 mm, 20x1, SMT; Manufacturer: AVX; SymbolCreator: Altium; Pitch_mm: 1.25; Gender: Female; Row_Count: 1
footprint Kyocera_006207332920
pins: 1, 2, 3, 4, 5, 6, 7, 8, 9, 10, 11, 12, 13, 14, 15, 16, 17, 18, 19, 20

## 006207341914000+
designator J?
Receptacle, 1.25mm, 14x1, Tin, R/A, SMT; Manufacturer: AVX; SymbolCreator: a0411947; Pitch_mm: 1.25; Gender: Female; Row_Count: 1; Voltage_V: 125
footprint AVX_006207341x14xxx+
pins: 1, 2, 3, 4, 5, 6, 7, 8, 9, 10, 11, 12, 13, 14

## 006208000130001+
designator J?  (value not drawn)
Receptacle, 1mm, 30x1, Gold, TH; Manufacturer: AVX; SymbolCreator: Altium; Pitch_mm: 1; Gender: Female
footprint Kyocera_006208000130001
pins: 1, 2, 3, 4, 5, 6, 7, 8, 9, 10, 11, 12, 13, 14, 15, 16, 17, 18, 19, 20, 21, 22, 23, 24, 25, 26, 27, 28, 29, 30

## 009155003301006
designator J?
Connector, Battery 3 Postion, R/A, SMT; Manufacturer: AVX; SymbolCreator: a0799628
footprint CONN_009155003301006
pins: 1, 2, 3
3 alternate drawings of the same symbol

## 009178001001006
designator J?
50 Ohm IDC Coax Connector, SMD; Manufacturer: AVX; SymbolCreator: Altium
footprint AVX_009178001001006
pins: 1, 2

## 15120202601000
designator J?  (value not drawn)
Header (Shrouded), 1.27mm, 10x2, Gold, Black, SMT; Manufacturer: Harting; SymbolCreator: Altium; Pitch_mm: 1.27; Gender: Male; Shrouded: Y; Row_Count: 2; Voltage_V: 500
footprint Harting_15120202601000
pins: A1, A2, A3, A4, A5, A6, A7, A8, A9, A10, B1, B2, B3, B4, B5, B6, B7, B8, B9, B10, MP1, MP2, MP3, MP4

## 15120322601000
designator J?  (value not drawn)
Header (Shrouded), 1.27mm, 16x2, Gold, Black, SMT; Manufacturer: Harting; SymbolCreator: Altium; Pitch_mm: 1.27; Gender: Male; Shrouded: Y; Row_Count: 2; Voltage_V: 500
footprint Harting_15120322601000
pins: A1, A2, A3, A4, A5, A6, A7, A8, A9, A10, A11, A12, A13, A14, A15, A16, B1, B2, B3, B4, B5, B6, B7, B8, B9, B10, B11, B12, B13, B14, B15, B16, MP1, MP2, MP3, MP4

## 15150202601000
designator J?  (value not drawn)
Header(shrouded), 1.27mm, 10x2, R/A, SMT; Manufacturer: Harting; SymbolCreator: Altium; Pitch_mm: 1.27; Gender: Male; Shrouded: Y; Row_Count: 2; Current_A: 1.7
footprint Harting_1515020X601XXX
pins: A1, A2, A3, A4, A5, A6, A7, A8, A9, A10, B1, B2, B3, B4, B5, B6, B7, B8, B9, B10, MP1, MP2, MP3, MP4

## 15150322601000
designator J?  (value not drawn)
Header(shrouded), 1.27mm, 16x2, R/A, SMT; Manufacturer: Harting; SymbolCreator: Altium; Pitch_mm: 1.27; Gender: Male; Shrouded: Y; Row_Count: 2; Current_A: 1.7
footprint Harting_1515032X601XXX
pins: A1, A2, A3, A4, A5, A6, A7, A8, A9, A10, A11, A12, A13, A14, A15, A16, B1, B2, B3, B4, B5, B6, B7, B8, B9, B10, B11, B12, B13, B14, B15, B16, MP1, MP2, MP3, MP4

## 15250202601000
designator J?
Receptacle, 10x2, 1.27mm, R/A, SMT; Manufacturer: Harting; SymbolCreator: Altium; Pitch_mm: 1.27; Gender: Female; Row_Count: 2; Current_A: 1.7; Cert_UL: Y
footprint Harting_1525020x601xxx
pins: A1, A2, A3, A4, A5, A6, A7, A8, A9, A10, B1, B2, B3, B4, B5, B6, B7, B8, B9, B10, MP1, MP2, MP3, MP4

## 15250322601000
designator J?  (value not drawn)
Receptacle, 16x2, 1.27mm, R/A, SMT; Manufacturer: Harting; SymbolCreator: Altium; Pitch_mm: 1.27; Gender: Female; Row_Count: 2; Current_A: 1.7; Cert_UL: Y
footprint Harting_1525032x601xxx
pins: A1, A2, A3, A4, A5, A6, A7, A8, A9, A10, A11, A12, A13, A14, A15, A16, B1, B2, B3, B4, B5, B6, B7, B8, B9, B10, B11, B12, B13, B14, B15, B16, MP1, MP2, MP3, MP4

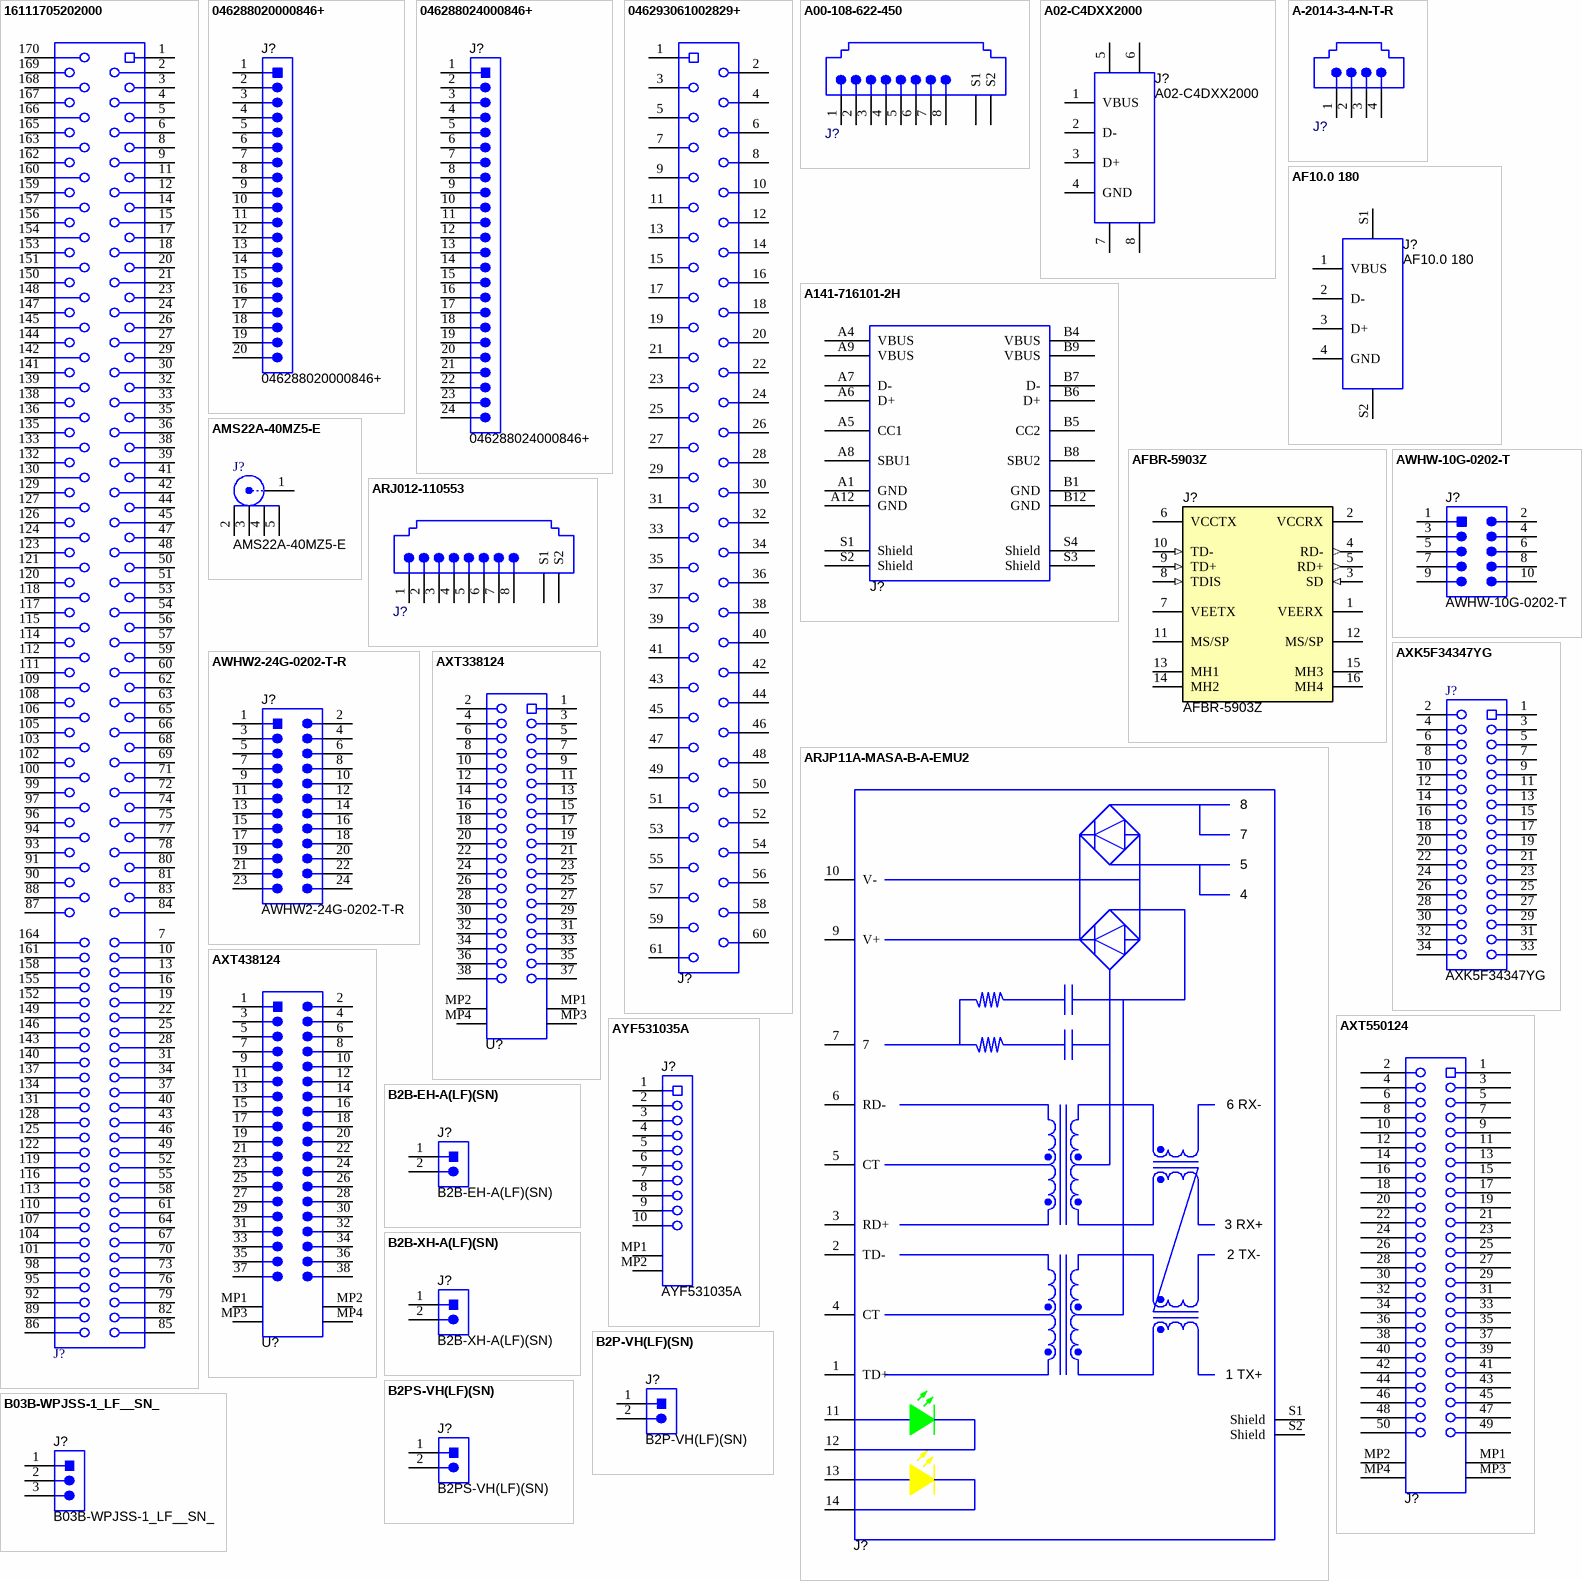
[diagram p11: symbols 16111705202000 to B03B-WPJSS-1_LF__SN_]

## 16111705202000
designator J?  (value not drawn)
Receptacle, 0.75mm, 85x2, Gold, TH; Manufacturer: Harting; SymbolCreator: Altium; Pitch_mm: 0.75; Gender: Female; Row_Count: 2
footprint Harting_16111705202000
pins: 1, 2, 3, 4, 5, 6, 7, 8, 9, 10, 11, 12, 13, 14, 15, 16, 17, 18, 19, 20, 21, 22, 23, 24, 25, 26, 27, 28, 29, 30, 31, 32, 33, 34, 35, 36, 37, 38, 39, 40, 41, 42, 43, 44, 45, 46, 47, 48, 49, 50, 51, 52, 53, 54, 55, 56, 57, 58, 59, 60, 61, 62, 63, 64, 65, 66, 67, 68, 69, 70, 71, 72, 73, 74, 75, 76, 77, 78, 79, 80, 81, 82, 83, 84, 85, 86, 87, 88, 89, 90, 91, 92, 93, 94, 95, 96, 97, 98, 99, 100, 101, 102, 103, 104, 105, 106, 107, 108, 109, 110, 111, 112, 113, 114, 115, 116, 117, 118, 119, 120, 121, 122, 123, 124, 125, 126, 127, 128, 129, 130, 131, 132, 133, 134, 135, 136, 137, 138, 139, 140, 141, 142, 143, 144, 145, 146, 147, 148, 149, 150, 151, 152, 153, 154, 155, 156, 157, 158, 159, 160, 161, 162, 163, 164, 165, 166, 167, 168, 169, 170

## 046288020000846+
designator J?
Connector, 20 Pos. 0.5mm R/A SMT Bottom Contact One-Touch Lock, SMT; Manufacturer: Kyocera; SymbolCreator: a0412235
footprint CONN_046288020000846+
pins: 1, 2, 3, 4, 5, 6, 7, 8, 9, 10, 11, 12, 13, 14, 15, 16, 17, 18, 19, 20

## 046288024000846+
designator J?
Connector, 24 Pos, 0.5mm R/A SMT Bottom Contact One-Touch Lock, SMT; Manufacturer: Kyocera; SymbolCreator: a0799628
footprint CONN_046288024000846+
pins: 1, 2, 3, 4, 5, 6, 7, 8, 9, 10, 11, 12, 13, 14, 15, 16, 17, 18, 19, 20, 21, 22, 23, 24

## 046293061002829+
designator J?  (value not drawn)
FPC Connector, 0.3mm, 61 Pos, R/A, SMT; Manufacturer: Kyocera; SymbolCreator: Altium; Pitch_mm: 0.3; Gender: Female; Row_Count: 1; Current_A: 0.2; Voltage_V: 50; Cert_UL: Y
footprint Kyocera_04_6293_061_002_829+
pins: 1, 2, 3, 4, 5, 6, 7, 8, 9, 10, 11, 12, 13, 14, 15, 16, 17, 18, 19, 20, 21, 22, 23, 24, 25, 26, 27, 28, 29, 30, 31, 32, 33, 34, 35, 36, 37, 38, 39, 40, 41, 42, 43, 44, 45, 46, 47, 48, 49, 50, 51, 52, 53, 54, 55, 56, 57, 58, 59, 60, 61

## A00-108-622-450
designator J?  (value not drawn)
RJ45, Shielded, Gold, TH; Manufacturer: Edac Inc.; SymbolCreator: Altium; Pitch_mm: 1.27; Gender: Female; Row_Count: 2; RowSpacing_mm: 2.54; Current_A: 1.5; Voltage_V: 125; Cert_UL: Y
footprint EDAC_A00-108-622-450
pins: 1, 2, 3, 4, 5, 6, 7, 8, S1, S2

## A02-C4DXX2000
designator J?
Connector, Receptacle, USB Type A, R/A, SMT; Manufacturer: Any; SymbolCreator: a0411947; Gender: Female; Row_Count: 1; Voltage_V: 500
footprint XNT_A02-C4DXX2000
pins: 1 VBUS "+5V", 2 D- "Data -", 3 D+ "Data +", 4 GND "Ground", 5 Shield, 6 Shield, 7 Shield, 8 Shield

## A141-716101-2H
designator J?  (value not drawn)
Receptacle, USB2.0, TYPE-C, R/A, SMT; Manufacturer: All Best Electronics; SymbolCreator: Altium; CompType: USB; Pitch_mm: 0.5; Gender: Female; Row_Count: 1; ContactFinish: Gold; Cert_UL: Y
footprint ALLBEST_A141-716101-2H
pins: A1 GND, A4 VBUS, A5 CC1, A6 D+, A7 D-, A8 SBU1, A9 VBUS, A12 GND, B1 GND, B4 VBUS, B5 CC2, B6 D+, B7 D-, B8 SBU2, B9 VBUS, B12 GND, S1 Shield, S2 Shield, S3 Shield, S4 Shield

## A-2014-3-4-N-T-R
designator J?  (value not drawn)
Modular Connector, Jack, 4P4C, Gold, TH; Manufacturer: Assman WSW; SymbolCreator: Altium; Pitch_mm: 1.27; Gender: Female; Row_Count: 2; RowSpacing_mm: 2.54; Current_A: 1.5; Voltage_V: 125; Cert_UL: Y
footprint Assman_A-2014-3-x-N-T-R
pins: 1, 2, 3, 4

## AF10.0 180
designator J?
USB socket A type, 4x1, Gold, TH; Manufacturer: Dongguan Jinbaoli Electronics Co., Ltd; SymbolCreator: Altium; Gender: Male; Shrouded: Y; Row_Count: 1
footprint DGJBL_AF10_0_180
pins: 1 VBUS "+5V", 2 D- "Data -", 3 D+ "Data +", 4 GND "Ground", S1, S2

## AFBR-5903Z
designator J?
FDDI, Fast Ethernet Transceivers, 5x2, TH; Manufacturer: Avago; SymbolCreator: Altium; CompType: Connector; Pitch_mm: 1.778; Gender: Female; Row_Count: 2; RowSpacing_mm: 10.16
footprint Avago_AFBR-5903Z
pins: 1 VEERX (power), 2 VCCRX (power), 3 SD (in), 4 RD- (out), 5 RD+ (out), 6 VCCTX (power), 7 VEETX (power), 8 TDIS (in), 9 TD+ (in), 10 TD- (in), 11 MS/SP, 12 MS/SP, 13 MH1 (power), 14 MH2 (power), 15 MH3 (power), 16 MH4 (power)

## AMS22A-40MZ5-E
designator J?
SMA Plug Connector, HFM, 50 Ohm, R/A, TH; Manufacturer: Rosenberger; SymbolCreator: X0208326; Gender: Male; Shrouded: Y; ContactFinish: Gold; Voltage_V: 335
footprint Rosenberger_AMS22A-40MZ5-E
pins: 1, 2, 3, 4, 5

## ARJ012-110553
designator J?  (value not drawn)
Connector, RJ45, R/A, TH; Manufacturer: Abracon Corporation; SymbolCreator: Altium; Pitch_mm: 1.27; Gender: Female; Row_Count: 2; RowSpacing_mm: 2.54; Current_A: 1.5; Voltage_V: 125
footprint Abracon_ARJ012-110553
pins: 1, 2, 3, 4, 5, 6, 7, 8, S1, S2

## ARJP11A-MASA-B-A-EMU2
designator J?  (value not drawn)
Connector, RJ45 with integrated magnetics, Gold, R/A, TH; Manufacturer: Abracon Corporation; SymbolCreator: Altium; Gender: Female
footprint Abracon_ARJP11A
pins: 1 TD+, 2 TD-, 3 RD+, 4 CT, 5 CT, 6 RD-, 7, 9 V+, 10 V-, 11 LEFT LED ANODE, 12 LEFT LED CATHODE, 13 RIGHT LED ANODE, 14 RIGHT LED CATHODE, S1 Shield, S2 Shield

## AWHW2-24G-0202-T-R
designator J?
Header (shrouded), 2mm, 12x2, Gold, TH; Manufacturer: Assman WSW; SymbolCreator: a0412235
footprint ASSMANN_AWHW2-24G-0202-T-R
pins: 1, 2, 3, 4, 5, 6, 7, 8, 9, 10, 11, 12, 13, 14, 15, 16, 17, 18, 19, 20, 21, 22, 23, 24

## AWHW-10G-0202-T
designator J?
Header(Shrouded), 2.54mm, 5x2, Gold, TH; Manufacturer: Assman WSW; SymbolCreator: a0412235; Pitch_mm: 2.54; Gender: Male; Shrouded: Y; Row_Count: 2; Green_Lifecycle: Active; Green_REACh: Passed
footprint Assman_AWHW-10G-0x02-T
pins: 1, 2, 3, 4, 5, 6, 7, 8, 9, 10

## AXK5F34347YG
designator J?
Socket, 0.5 mm, 17x2, Gold, SMD; Manufacturer: Panasonic; SymbolCreator: a0411947
footprint Panasonic_ AXK5F34347YG
pins: 1, 2, 3, 4, 5, 6, 7, 8, 9, 10, 11, 12, 13, 14, 15, 16, 17, 18, 19, 20, 21, 22, 23, 24, 25, 26, 27, 28, 29, 30, 31, 32, 33, 34

## AXT338124
designator U?  (value not drawn)
Socket, 0.4mm, 19x2, Gold, SMT; Manufacturer: Panasonic; SymbolCreator: Altium; Pitch_mm: 0.4; Gender: Female; Row_Count: 2; Current_A: 0.3; Voltage_V: 60; Cert_UL: Y
footprint Panasonic_ AXT338124
pins: 1, 2, 3, 4, 5, 6, 7, 8, 9, 10, 11, 12, 13, 14, 15, 16, 17, 18, 19, 20, 21, 22, 23, 24, 25, 26, 27, 28, 29, 30, 31, 32, 33, 34, 35, 36, 37, 38, MP1, MP2, MP3, MP4

## AXT438124
designator U?  (value not drawn)
Header(shrouded), 0.4mm, 19x2, Gold, SMT; Manufacturer: Panasonic; SymbolCreator: Altium; Pitch_mm: 0.4; Gender: Male; Shrouded: Y; Row_Count: 2; Current_A: 0.3; Voltage_V: 60
footprint Panasonic_ AXT438124
pins: 1, 2, 3, 4, 5, 6, 7, 8, 9, 10, 11, 12, 13, 14, 15, 16, 17, 18, 19, 20, 21, 22, 23, 24, 25, 26, 27, 28, 29, 30, 31, 32, 33, 34, 35, 36, 37, 38, MP1, MP2, MP3, MP4

## AXT550124
designator J?  (value not drawn)
Socket, 0.4mm, 25x2, Gold, SMT; Manufacturer: Panasonic; SymbolCreator: Altium; Pitch_mm: 0.4; Gender: Female; Row_Count: 2; Current_A: 5; Voltage_V: 60; Cert_UL: Y
footprint Panasonic_AXT550124
pins: 1, 2, 3, 4, 5, 6, 7, 8, 9, 10, 11, 12, 13, 14, 15, 16, 17, 18, 19, 20, 21, 22, 23, 24, 25, 26, 27, 28, 29, 30, 31, 32, 33, 34, 35, 36, 37, 38, 39, 40, 41, 42, 43, 44, 45, 46, 47, 48, 49, 50, MP1, MP2, MP3, MP4

## AYF531035A
designator J?
Receptacle, 0.5mm, 10x1, Gold, R/A, SMD; Manufacturer: Panasonic; SymbolCreator: Altium; Pitch_mm: 0.5; Gender: Female; Row_Count: 1; Voltage_V: 50; Cert_UL: Y
footprint Panasonic_ AYF531035
pins: 1, 2, 3, 4, 5, 6, 7, 8, 9, 10, MP1, MP2

## B2B-EH-A(LF)(SN)
designator J?
Header (Shrouded), 2.5mm, 2x1, Tin, TH; Manufacturer: JST Manufacturing; SymbolCreator: a0412235; Pitch_mm: 2.5; Gender: Male; Shrouded: Y; Row_Count: 1; Current_A: 3; Voltage_V: 250
footprint JST_B2B-EH-A
pins: 1, 2
1 alternate drawing of the same symbol

## B2B-XH-A(LF)(SN)
designator J?
Header (Shrouded), 2.5mm, 2x1, Tin, TH; Manufacturer: JST Manufacturing; SymbolCreator: a0412235; Pitch_mm: 2.5; Gender: Male; Shrouded: Y; Row_Count: 1; Current_A: 3; Voltage_V: 250
footprint JST_B2B-XH-A
pins: 1, 2
1 alternate drawing of the same symbol

## B2P-VH(LF)(SN)
designator J?
Header, 3.96 mm, 2x1, Tin, TH; Manufacturer: JST Manufacturing; SymbolCreator: a0412235; Green_Lifecycle: Active; Green_REACh: Passed
footprint JST_B2P-VH
pins: 1, 2
1 alternate drawing of the same symbol

## B2PS-VH(LF)(SN)
designator J?
Header (friction lock), 3.96mm, 2x1, Tin, R/A, TH; Manufacturer: JST Manufacturing; SymbolCreator: a0412235; Green_Lifecycle: Active; Green_REACh: Passed
footprint JST_B2PS-VH
pins: 1, 2
1 alternate drawing of the same symbol

## B03B-WPJSS-1_LF__SN_
designator J?
Header (Shrouded), 5 mm, 3x1, Tin, TH; Manufacturer: JST Manufacturing; SymbolCreator: a0799628
footprint JST_B03B-WPJSS-1
pins: 1, 2, 3
3 alternate drawings of the same symbol

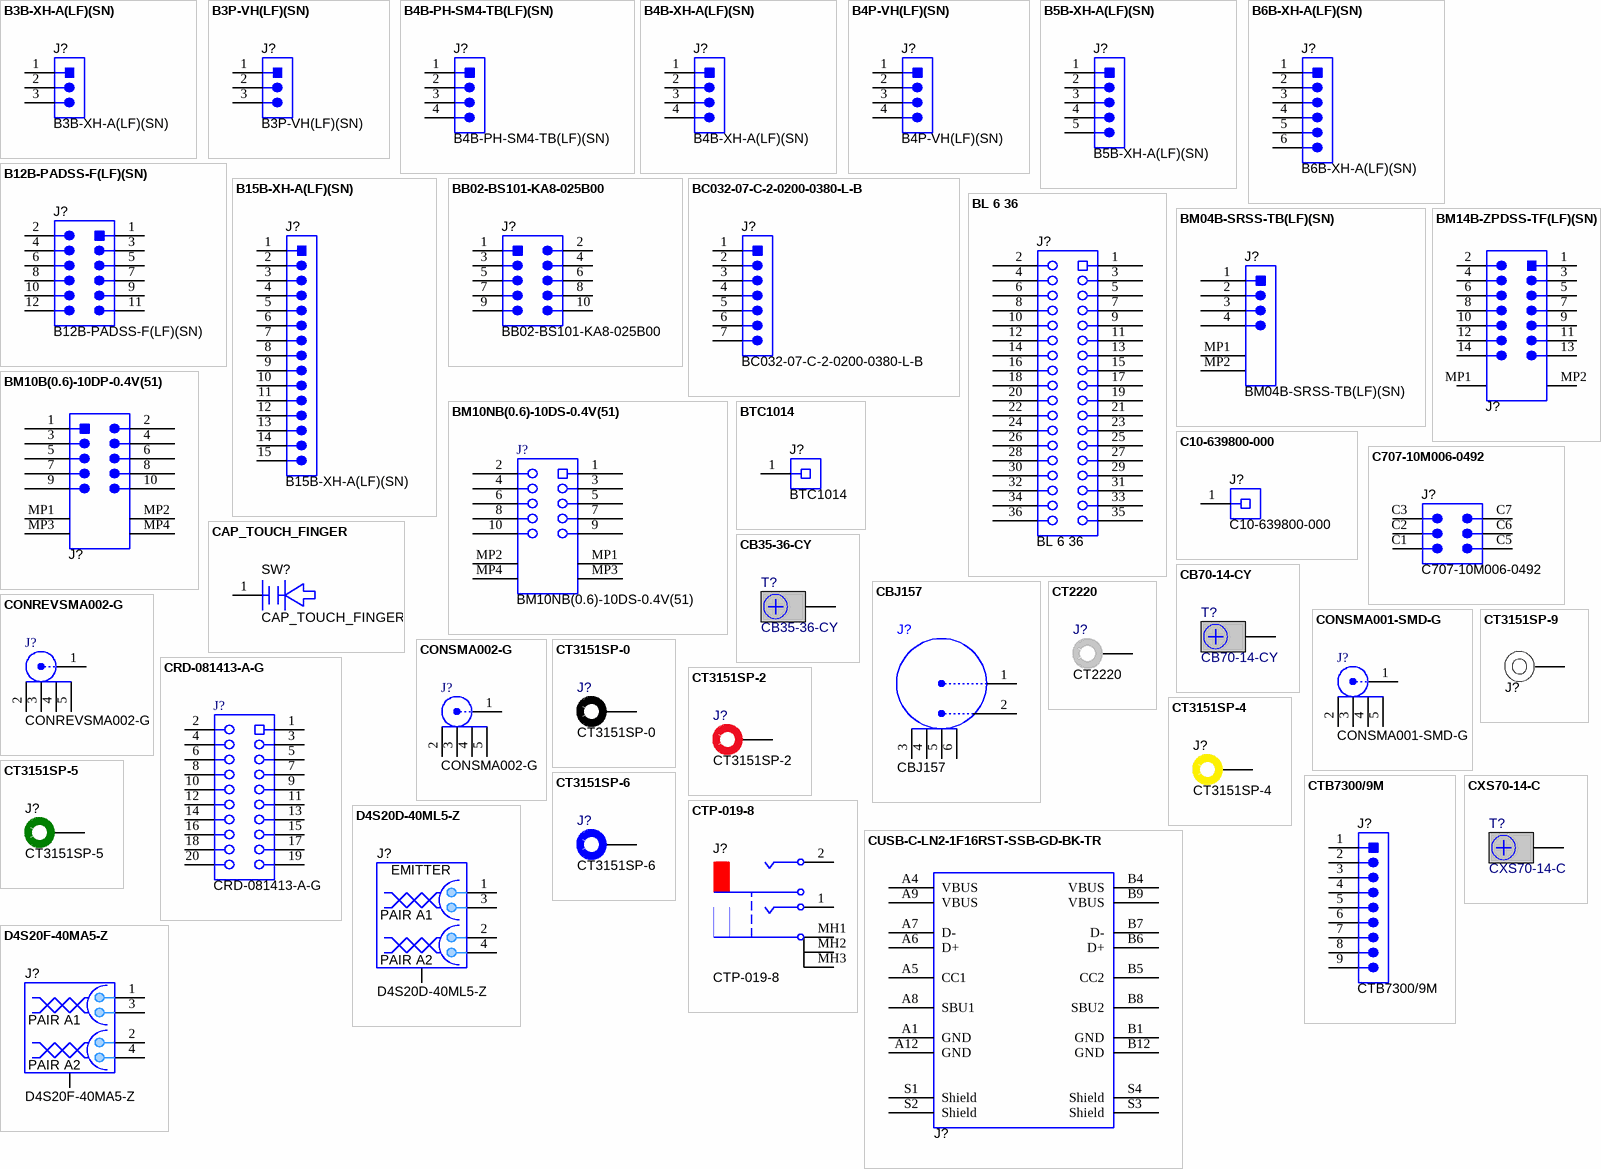
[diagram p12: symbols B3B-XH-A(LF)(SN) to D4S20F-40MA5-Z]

## B3B-XH-A(LF)(SN)
designator J?
Header (Shrouded), 2.5mm, 3x1, Tin, TH; Manufacturer: JST Manufacturing; SymbolCreator: a0799628; Pitch_mm: 2.5; Gender: Male; Shrouded: Y; Row_Count: 1; Current_A: 3; Voltage_V: 250
footprint JST_B3B-XH-A
pins: 1, 2, 3
3 alternate drawings of the same symbol

## B3P-VH(LF)(SN)
designator J?
Header (Shrouded), 3.96mm, 3x1, Tin, TH; Manufacturer: JST Manufacturing; SymbolCreator: a0799628; Pitch_mm: 3.96; Gender: Male; Shrouded: Y; Row_Count: 1; Current_A: 10; Voltage_V: 250
footprint JST_B3P-VH
pins: 1, 2, 3
3 alternate drawings of the same symbol

## B4B-PH-SM4-TB(LF)(SN)
designator J?
Header(shrouded), 2mm, 4x1, Tin, Natural, SMT; Manufacturer: JST Manufacturing; SymbolCreator: a0412235; Pitch_mm: 2; Gender: Male; Shrouded: Y; Row_Count: 1; Voltage_V: 100
footprint JST_B4B-PH-SM4-TB
pins: 1, 2, 3, 4

## B4B-XH-A(LF)(SN)
designator J?
Header (Shrouded), 2.5mm, 4x1, Tin, TH; Manufacturer: JST Manufacturing; SymbolCreator: a0412235; Pitch_mm: 2.5; Gender: Male; Shrouded: Y; Row_Count: 1; Current_A: 3; Voltage_V: 250
footprint JST_B4B-XH-A
pins: 1, 2, 3, 4

## B4P-VH(LF)(SN)
designator J?
Header, 3.96 mm, 4x1, Tin, TH; Manufacturer: JST Manufacturing; SymbolCreator: a0412235
footprint JST_B4P-VH
pins: 1, 2, 3, 4

## B5B-XH-A(LF)(SN)
designator J?
Header(shrouded), 2.5mm, 5x1, Tin, TH; Manufacturer: JST Manufacturing; SymbolCreator: a0412235; Pitch_mm: 2.5; Gender: Male; Shrouded: Y; Row_Count: 1; Current_A: 3; Voltage_V: 250
footprint JST_B5B-XH-A
pins: 1, 2, 3, 4, 5

## B6B-XH-A(LF)(SN)
designator J?
Header (Shrouded), 2.5mm, 6x1, Tin, TH; Manufacturer: JST Manufacturing; SymbolCreator: a0412235; Pitch_mm: 2.5; Gender: Male; Shrouded: Y; Row_Count: 1; Current_A: 3; Voltage_V: 250
footprint JST_B6B-XH-A
pins: 1, 2, 3, 4, 5, 6

## B12B-PADSS-F(LF)(SN)
designator J?
Header(Shrouded), 2mm, 6x2, Tin, TH; Manufacturer: JST Manufacturing; SymbolCreator: Altium; Pitch_mm: 2; Gender: Male; Shrouded: Y; Current_A: 3; Voltage_V: 250
footprint JST_B12B-PADSS-F
pins: 1, 2, 3, 4, 5, 6, 7, 8, 9, 10, 11, 12
1 alternate drawing of the same symbol

## B15B-XH-A(LF)(SN)
designator J?
Header (Shrouded), 2.5 mm, 15x1, TH; Manufacturer: JST Manufacturing; SymbolCreator: Altium
footprint JST_B15B-XH-A
pins: 1, 2, 3, 4, 5, 6, 7, 8, 9, 10, 11, 12, 13, 14, 15

## BB02-BS101-KA8-025B00
designator J?
Header, 1.27mm, 5x2, SMT; Manufacturer: GradConn; SymbolCreator: a0412235; Pitch_mm: 1.27; Gender: Male; Shrouded: N; Row_Count: 2; ContactFinish: Gold
footprint Gradconn_BB02-BS101-xAx-025B00
pins: 1, 2, 3, 4, 5, 6, 7, 8, 9, 10

## BC032-07-C-2-0200-0380-L-B
designator J?
Header, 1mm, 7x1, Tin, SMT; Manufacturer: GCT; SymbolCreator: a0411947; Pitch_mm: 1; Gender: Male; Shrouded: N
footprint GCT_BC032-07-x-2-0200-0380
pins: 1, 2, 3, 4, 5, 6, 7

## BL 6 36
designator J?
Receptacle, 2.54mm, 18x2, TH; Manufacturer: Fischer Elektronik; SymbolCreator: a0411947
footprint Fischer_BL-6-36
pins: 1, 2, 3, 4, 5, 6, 7, 8, 9, 10, 11, 12, 13, 14, 15, 16, 17, 18, 19, 20, 21, 22, 23, 24, 25, 26, 27, 28, 29, 30, 31, 32, 33, 34, 35, 36

## BM04B-SRSS-TB(LF)(SN)
designator J?
Header(shrouded), 1mm, 4x1, Tin, SMT; Manufacturer: JST Manufacturing; SymbolCreator: Altium; Pitch_mm: 1; Gender: Male; Shrouded: Y; Voltage_V: 50
footprint JST_BM04B-SRSS-TB
pins: 1, 2, 3, 4, MP1, MP2

## BM10B(0.6)-10DP-0.4V(51)
designator J?  (value not drawn)
Header (Shrouded), 0.4mm, 5x2, Gold, SMT; Manufacturer: Hirose Electric Co. Ltd.; SymbolCreator: Altium; Pitch_mm: 2.54; Gender: Male; Shrouded: Y; Row_Count: 2; Current_A: 0.3; Voltage_V: 30
footprint Hirose_BM10B_0_6-10DP-0_4V
pins: 1, 2, 3, 4, 5, 6, 7, 8, 9, 10, MP1, MP2, MP3, MP4

## BM10NB(0.6)-10DS-0.4V(51)
designator J?
Receptacle, 0.4mm, 5x2, Gold, SMT; Manufacturer: Hirose Electric Co. Ltd.; SymbolCreator: Altium; Pitch_mm: 2.54; Gender: Female; Row_Count: 2; Current_A: 0.3; Voltage_V: 30
footprint Hirose_BM10NB_0_6-10DS-0_4V
pins: 1, 2, 3, 4, 5, 6, 7, 8, 9, 10, MP1, MP2, MP3, MP4

## BM14B-ZPDSS-TF(LF)(SN)
designator J?  (value not drawn)
Header(shrouded), 1.5mm, 7x2, Tin, SMT; Manufacturer: JST Manufacturing; SymbolCreator: Altium; Pitch_mm: 1.5; Gender: Male; Shrouded: Y; Row_Count: 2; RowSpacing_mm: 7.25; Voltage_V: 100
footprint JST_BM14B-ZPDSS-TF
pins: 1, 2, 3, 4, 5, 6, 7, 8, 9, 10, 11, 12, 13, 14, MP1, MP2

## BTC1014
designator J?
Type BTC - Copper Single-Conductor, TH; Manufacturer: Thomas & Betts; SymbolCreator: a0799628; CompType: Connector; Gender: Female; Row_Count: 1; Cert_UL: Y
footprint TB_BTC1014
pins: 1

## C10-639800-000
designator J?
5.7MM RADSOK, 10 Pos, TH; Manufacturer: Amphenol Connex; SymbolCreator: a0799628; CompType: Connector; Pitch_mm: 2.2; Gender: Female; Row_Count: 2; RowSpacing_mm: 13.3; Current_A: 120
footprint Amphenol_C10-639800-000
pins: 1

## C707-10M006-0492
designator J?
Connector, 6-Pos SIMLOCK,2.54mm, SMD; Manufacturer: Amphenol-Tuchel Electronics; SymbolCreator: a0799721
footprint CONN_C707-10M006-0492
pins: C1, C2, C3, C5, C6, C7

## CAP_TOUCH_FINGER
designator SW?
Scissor Type, Capacitive Touch Finger; Manufacturer: Texas Instruments; SymbolCreator: Altium; CompType: Connector
footprint TI_CAP_TOUCH_FINGER
pins: 1

## CB35-36-CY
designator T?
Terminal 50A Lug; Manufacturer: Panduit; SymbolCreator: crossc; CompType: Screw Terminal; ContactFinish: Copper; Voltage_V: 600; Cert_CULUS: Y; Green_Lifecycle: Not Set; Green_REACh: Incomplete
footprint CB35-36-CY
pins: 1

## CB70-14-CY
designator T?
Terminal 90A Lug; Manufacturer: Panduit; SymbolCreator: crossc; CompType: Screw Terminal; ContactFinish: Copper; Voltage_V: 600; Cert_CULUS: Y; Green_Lifecycle: Not Set; Green_REACh: Incomplete
footprint CB70-14-CY
pins: 1

## CBJ157
designator J?
Conn Female Triaxial, TH; Manufacturer: Cinch Connectivity; SymbolCreator: x0208326; CompType: Connector
footprint Emerson_CBJ157
pins: 1, 2, 3, 4, 5, 6

## CONREVSMA002-G
designator J?
SMA Jack, 50Ohm, R/A, TH; Manufacturer: Linx Technologies; SymbolCreator: X0208326; Gender: Male; ContactFinish: Gold
footprint Linx_CONREVSMA002-G
pins: 1, 2, 3, 4, 5

## CONSMA001-SMD-G
designator J?
Jack, SMA, PCB, Gold, SMT; Manufacturer: Linx Technologies; SymbolCreator: X0208326
footprint Linx_CONSMA001-SMD-G
pins: 1, 2, 3, 4, 5

## CONSMA002-G
designator J?
JACK, SMA, 50 Ohm, Gold, R/A, TH; Manufacturer: Linx Technologies; SymbolCreator: X0208326; Gender: Female
footprint Linx_CONSMA002-G
pins: 1, 2, 3, 4, 5

## CRD-081413-A-G
designator J?
Receptacle, 2.54 mm, 10x2, Gold, TH; Manufacturer: Major League Electronics; SymbolCreator: a0412235; Green_Lifecycle: Not Set; Green_REACh: Incomplete
footprint Major_CRD-081413-A-x
pins: 1, 2, 3, 4, 5, 6, 7, 8, 9, 10, 11, 12, 13, 14, 15, 16, 17, 18, 19, 20

## CT2220
designator J?
Banana Jack Connector Standard Banana Threaded, External (Nut), TH; Manufacturer: BK Precision; Gender: Female; ContactFinish: Nickel; Current_A: 36
footprint BKP_CT2220
pins: 1

## CT3151SP-0
designator J?
Banana Jack Insul Nylon Black, R/A, TH; Manufacturer: Cal Test Electronics; SymbolCreator: a0412235; Gender: Female; Row_Count: 1; ContactFinish: Nickel; Current_A: 25; Voltage_V: 1000; Cert_UL: Y
footprint CTE_CT3151SP-0
pins: 1

## CT3151SP-2
designator J?
Banana Jack Insul Nylon Red, R/A, TH; Manufacturer: Cal Test Electronics; SymbolCreator: a0412235; Gender: Female; Row_Count: 1; ContactFinish: Nickel; Current_A: 25; Voltage_V: 1000; Cert_UL: Y
footprint CTE_CT3151SP-2
pins: 1

## CT3151SP-4
designator J?
Banana Jack Insul Nylon Yellow, R/A, TH; Manufacturer: Cal Test Electronics; SymbolCreator: a0799721; Gender: Female; Row_Count: 1; ContactFinish: Nickel; Current_A: 25; Voltage_V: 1000; Cert_UL: Y
footprint CTE_CT3151SP-4
pins: 1

## CT3151SP-5
designator J?
Banana Jack Insul Nylon Green, R/A, TH; Manufacturer: Cal Test Electronics; SymbolCreator: a0411947; Gender: Female; Row_Count: 1; ContactFinish: Nickel; Current_A: 25; Voltage_V: 1000; Cert_UL: Y
footprint CTE_CT3151SP-5
pins: 1

## CT3151SP-6
designator J?
Banana Jack Insul Nylon Blue, R/A, TH; Manufacturer: Cal Test Electronics; SymbolCreator: a0411947; Gender: Female; Row_Count: 1; ContactFinish: Nickel; Current_A: 25; Voltage_V: 1000; Cert_UL: Y
footprint CTE_CT3151SP-6
pins: 1

## CT3151SP-9
designator J?  (value not drawn)
Banana Jack Insul Nylon White, R/A, TH; Manufacturer: Cal Test Electronics; SymbolCreator: Altium; Gender: Female; Row_Count: 1; ContactFinish: Nickel; Current_A: 25; Voltage_V: 1000; Cert_UL: Y
footprint CTE_CT3151SP-9
pins: 1

## CTB7300/9M
designator J?
Connector, Male Vertical 9x1, 5mm Pitch, TH; Manufacturer: Camden Boss; SymbolCreator: a0799628
footprint CONN_CTB7300_9M
pins: 1, 2, 3, 4, 5, 6, 7, 8, 9

## CTP-019-8
designator J?
Phono Jack, R/A, TH; Manufacturer: Connect-Tech-Products; SymbolCreator: x0411947; CompType: Audio Connector; Green_Lifecycle: Not Set; Green_REACh: Incomplete
footprint Connect-Tech_CTP-019-8
pins: 1 "Tip/Left Channel/(+)", 2 (power) "Sleeve (Ground)", MH1, MH2, MH3

## CUSB-C-LN2-1F16RST-SSB-GD-BK-TR
designator J?  (value not drawn)
Receptacle, USB2.0, TYPE-C, Gold, R/A, Black, SMT; Manufacturer: Central Semiconductor; SymbolCreator: Altium; CompType: USB; Pitch_mm: 0.5; Gender: Female; Row_Count: 1; Current_A: 3; Voltage_V: 100
footprint Central_CUSB-C-LN2-1F16RST-xxx-xx-BK
pins: A1 GND, A4 VBUS, A5 CC1, A6 D+, A7 D-, A8 SBU1, A9 VBUS, A12 GND, B1 GND, B4 VBUS, B5 CC2, B6 D+, B7 D-, B8 SBU2, B9 VBUS, B12 GND, S1 Shield, S2 Shield, S3 Shield, S4 Shield

## CXS70-14-C
designator T?
Terminal 70A Lug; Manufacturer: Panduit; SymbolCreator: crossc; CompType: Screw Terminal; Green_Lifecycle: Not Set; Green_REACh: Incomplete
footprint Panduit_CXS70-14-C
pins: 1

## D4S20D-40ML5-Z
designator J?
HSD Right Angle Plug for PCB, TH; Manufacturer: Rosenberger; SymbolCreator: Altium/a0412235; Green_Lifecycle: Not Set; Green_REACh: Incomplete
footprint Rosenberger_D4S20L-40MA5
footprint Rosenberger_D4S20L-40MA5_NoTopLayerPads
pins: 1, 2, 3, 4, MH
1 alternate drawing of the same symbol

## D4S20F-40MA5-Z
designator J?
HSD Right Angle Plug, 4-Leads, 2mm Pitch, TH; Manufacturer: Rosenberger; SymbolCreator: Altium; Pitch_mm: 2; Gender: Male; ContactFinish: Gold; Current_A: 1.5; Voltage_V: 100
footprint Rosenberger_D4S20F-40MA5
pins: 1, 2, 3, 4, MH

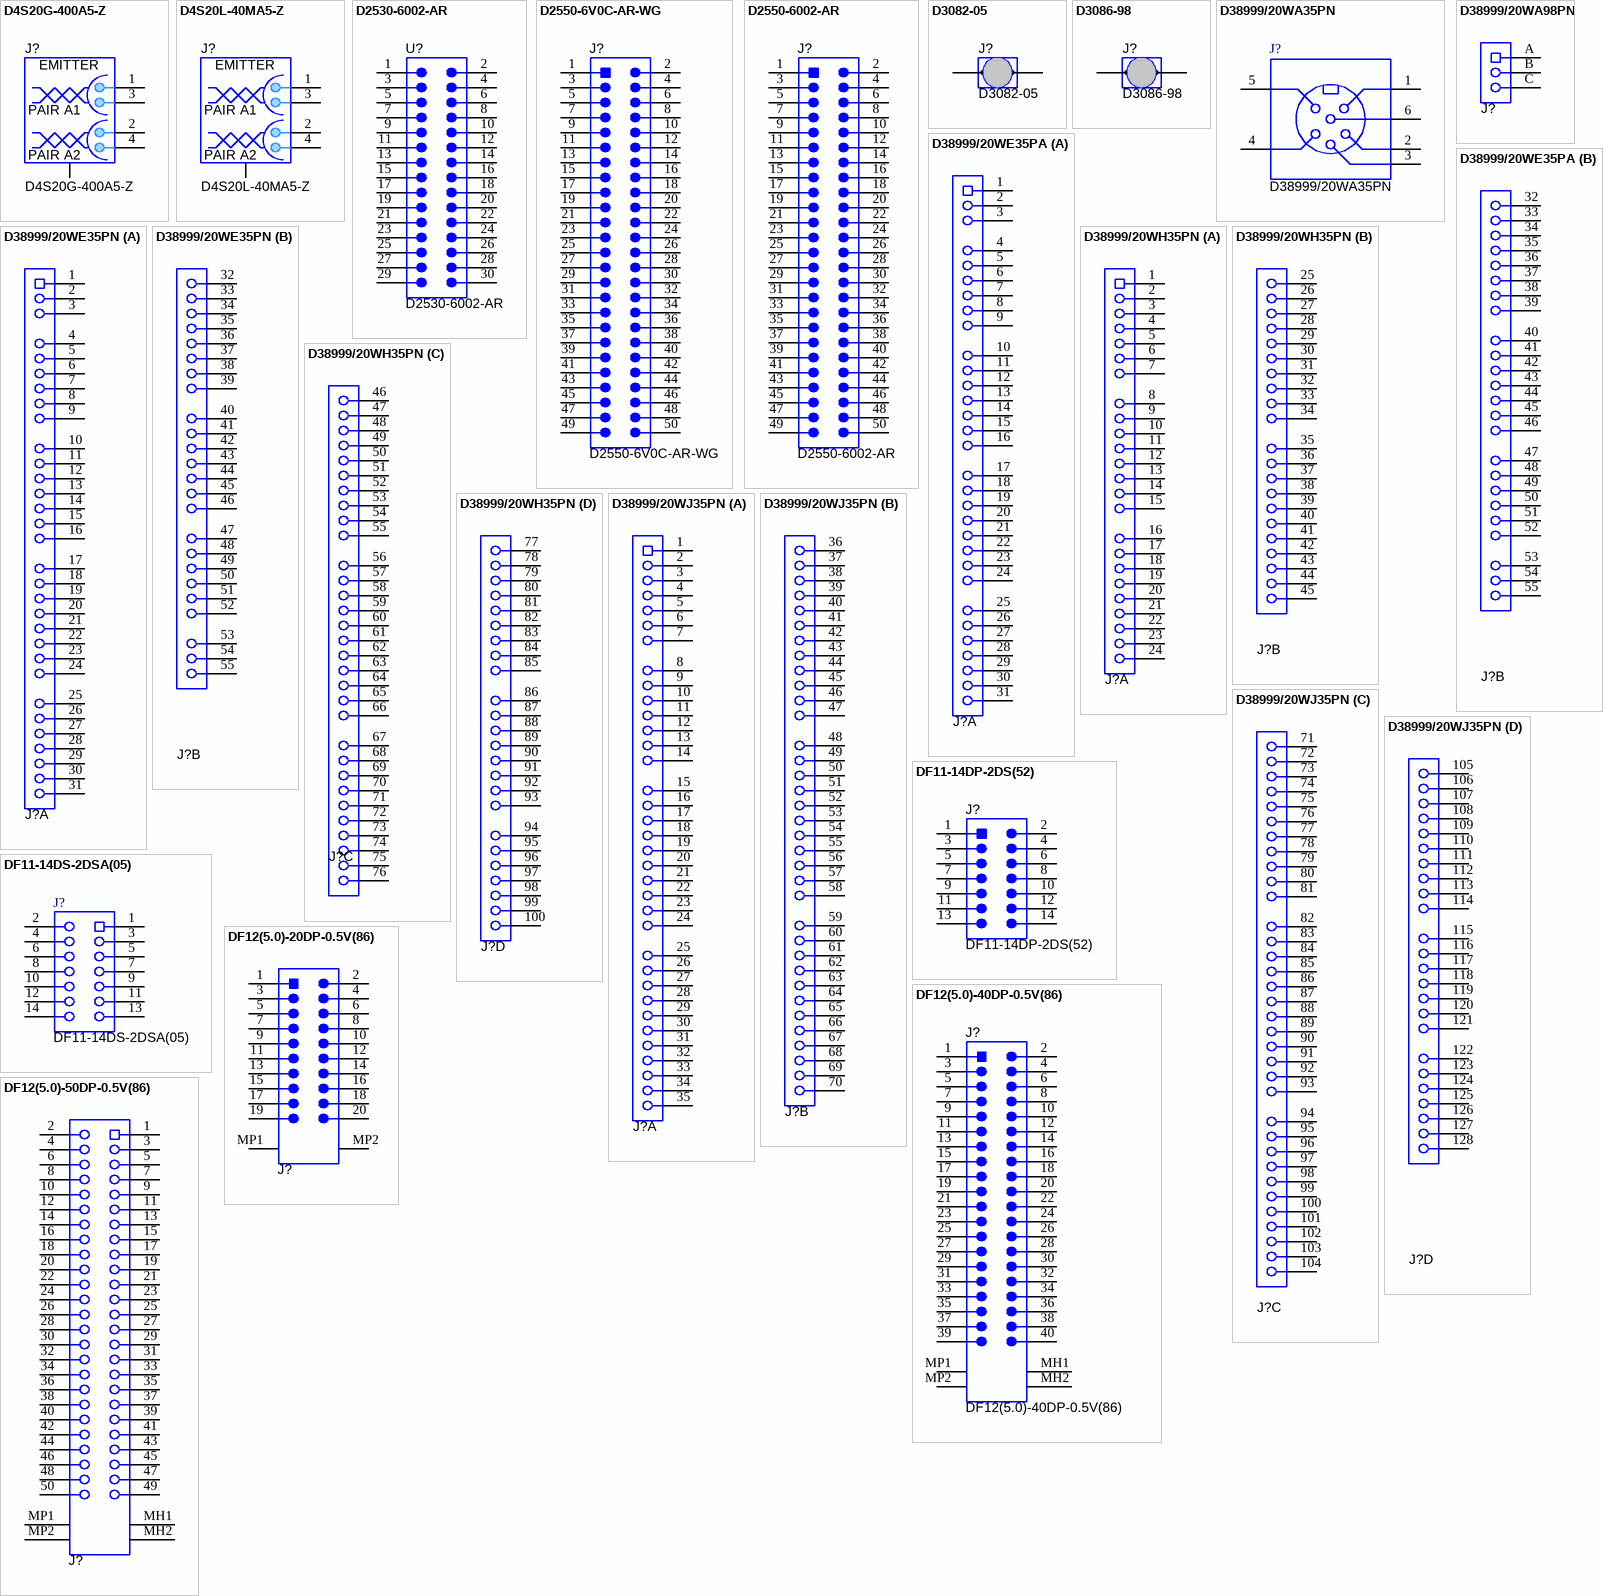
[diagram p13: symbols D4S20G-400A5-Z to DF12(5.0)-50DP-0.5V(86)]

## D4S20G-400A5-Z
designator J?
Right Angle Plug for PCB, TH; Manufacturer: Rosenberger; SymbolCreator: Altium/a0412235; Green_Lifecycle: Not Set; Green_REACh: Incomplete
footprint Rosenberger_D4S20G-400A5
pins: 1, 2, 3, 4, MH
1 alternate drawing of the same symbol

## D4S20L-40MA5-Z
designator J?
Right Angle Plug for PCB, TH; Manufacturer: Rosenberger; SymbolCreator: Altium/a0412235
footprint Rosenberger_D4S20L-40MA5
footprint Rosenberger_D4S20L-40MA5_NoTopLayerPads
pins: 1, 2, 3, 4, MH
1 alternate drawing of the same symbol

## D2530-6002-AR
designator U?
Header (shrouded), 100mil, 15x2, Gold, TH; Manufacturer: 3M; SymbolCreator: a0411947
footprint CONN_D2530-6002-AR
pins: 1 DAC0, 2 GPIO12, 3 +5V, 4 GND, 5 PWM3, 6 GND, 7 DAC1, 8 GND, 9 NC, 10 NC, 11 GPIO7, 12 GPIO6, 13 GPIO5, 14 GPIO4, 15 3.3V, 16 GND, 17 GPIO3, 18 GPIO2, 19 GPIO1, 20 GPIO0, 21 NC, 22 NC, 23 ADC0, 24 ADC1, 25 GPIO9, 26 GPIO8, 27 GND, 28 GND, 29 GPIO11, 30 GPIO10
1 alternate drawing of the same symbol

## D2550-6V0C-AR-WG
designator J?
Connector Header, 2.54mm, 25x2, Gold, SMT; Manufacturer: 3M; SymbolCreator: a0799628; Pitch_mm: 2.54; Gender: Male; Shrouded: Y; Row_Count: 2; Current_A: 1.75; Voltage_V: 500
footprint 3M_D2550-6V0C-AR
pins: 1, 2, 3, 4, 5, 6, 7, 8, 9, 10, 11, 12, 13, 14, 15, 16, 17, 18, 19, 20, 21, 22, 23, 24, 25, 26, 27, 28, 29, 30, 31, 32, 33, 34, 35, 36, 37, 38, 39, 40, 41, 42, 43, 44, 45, 46, 47, 48, 49, 50

## D2550-6002-AR
designator J?
Header(shrouded), 2.54mm, 25x2, Gold, TH; Manufacturer: 3M; SymbolCreator: a0799628; Pitch_mm: 2.54; Gender: Male; Shrouded: Y; Row_Count: 2; Current_A: 1.75
footprint 3M_D2550-6002
pins: 1, 2, 3, 4, 5, 6, 7, 8, 9, 10, 11, 12, 13, 14, 15, 16, 17, 18, 19, 20, 21, 22, 23, 24, 25, 26, 27, 28, 29, 30, 31, 32, 33, 34, 35, 36, 37, 38, 39, 40, 41, 42, 43, 44, 45, 46, 47, 48, 49, 50

## D3082-05
designator J?
1mm Uninsulated Shorting Plug, 10.16mm spacing, TH; Manufacturer: Harwin; SymbolCreator: a0799628; CompType: Jumper Wire; Green_Lifecycle: Active; Green_REACh: Passed
footprint Harwin_D3082-05
pins: 1, 2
